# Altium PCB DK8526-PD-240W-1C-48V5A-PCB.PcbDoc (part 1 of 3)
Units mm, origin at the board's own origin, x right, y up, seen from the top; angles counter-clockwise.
Board outline 89.28 x 73.8 mm, 4 copper layers (Top Layer, Layer 1, Layer 2, Bottom Layer), stack 0.603 mm thick; 182 components, 162 nets, 518 pads, 506 vias.
Unrouted connection lines stored in the file: 4.
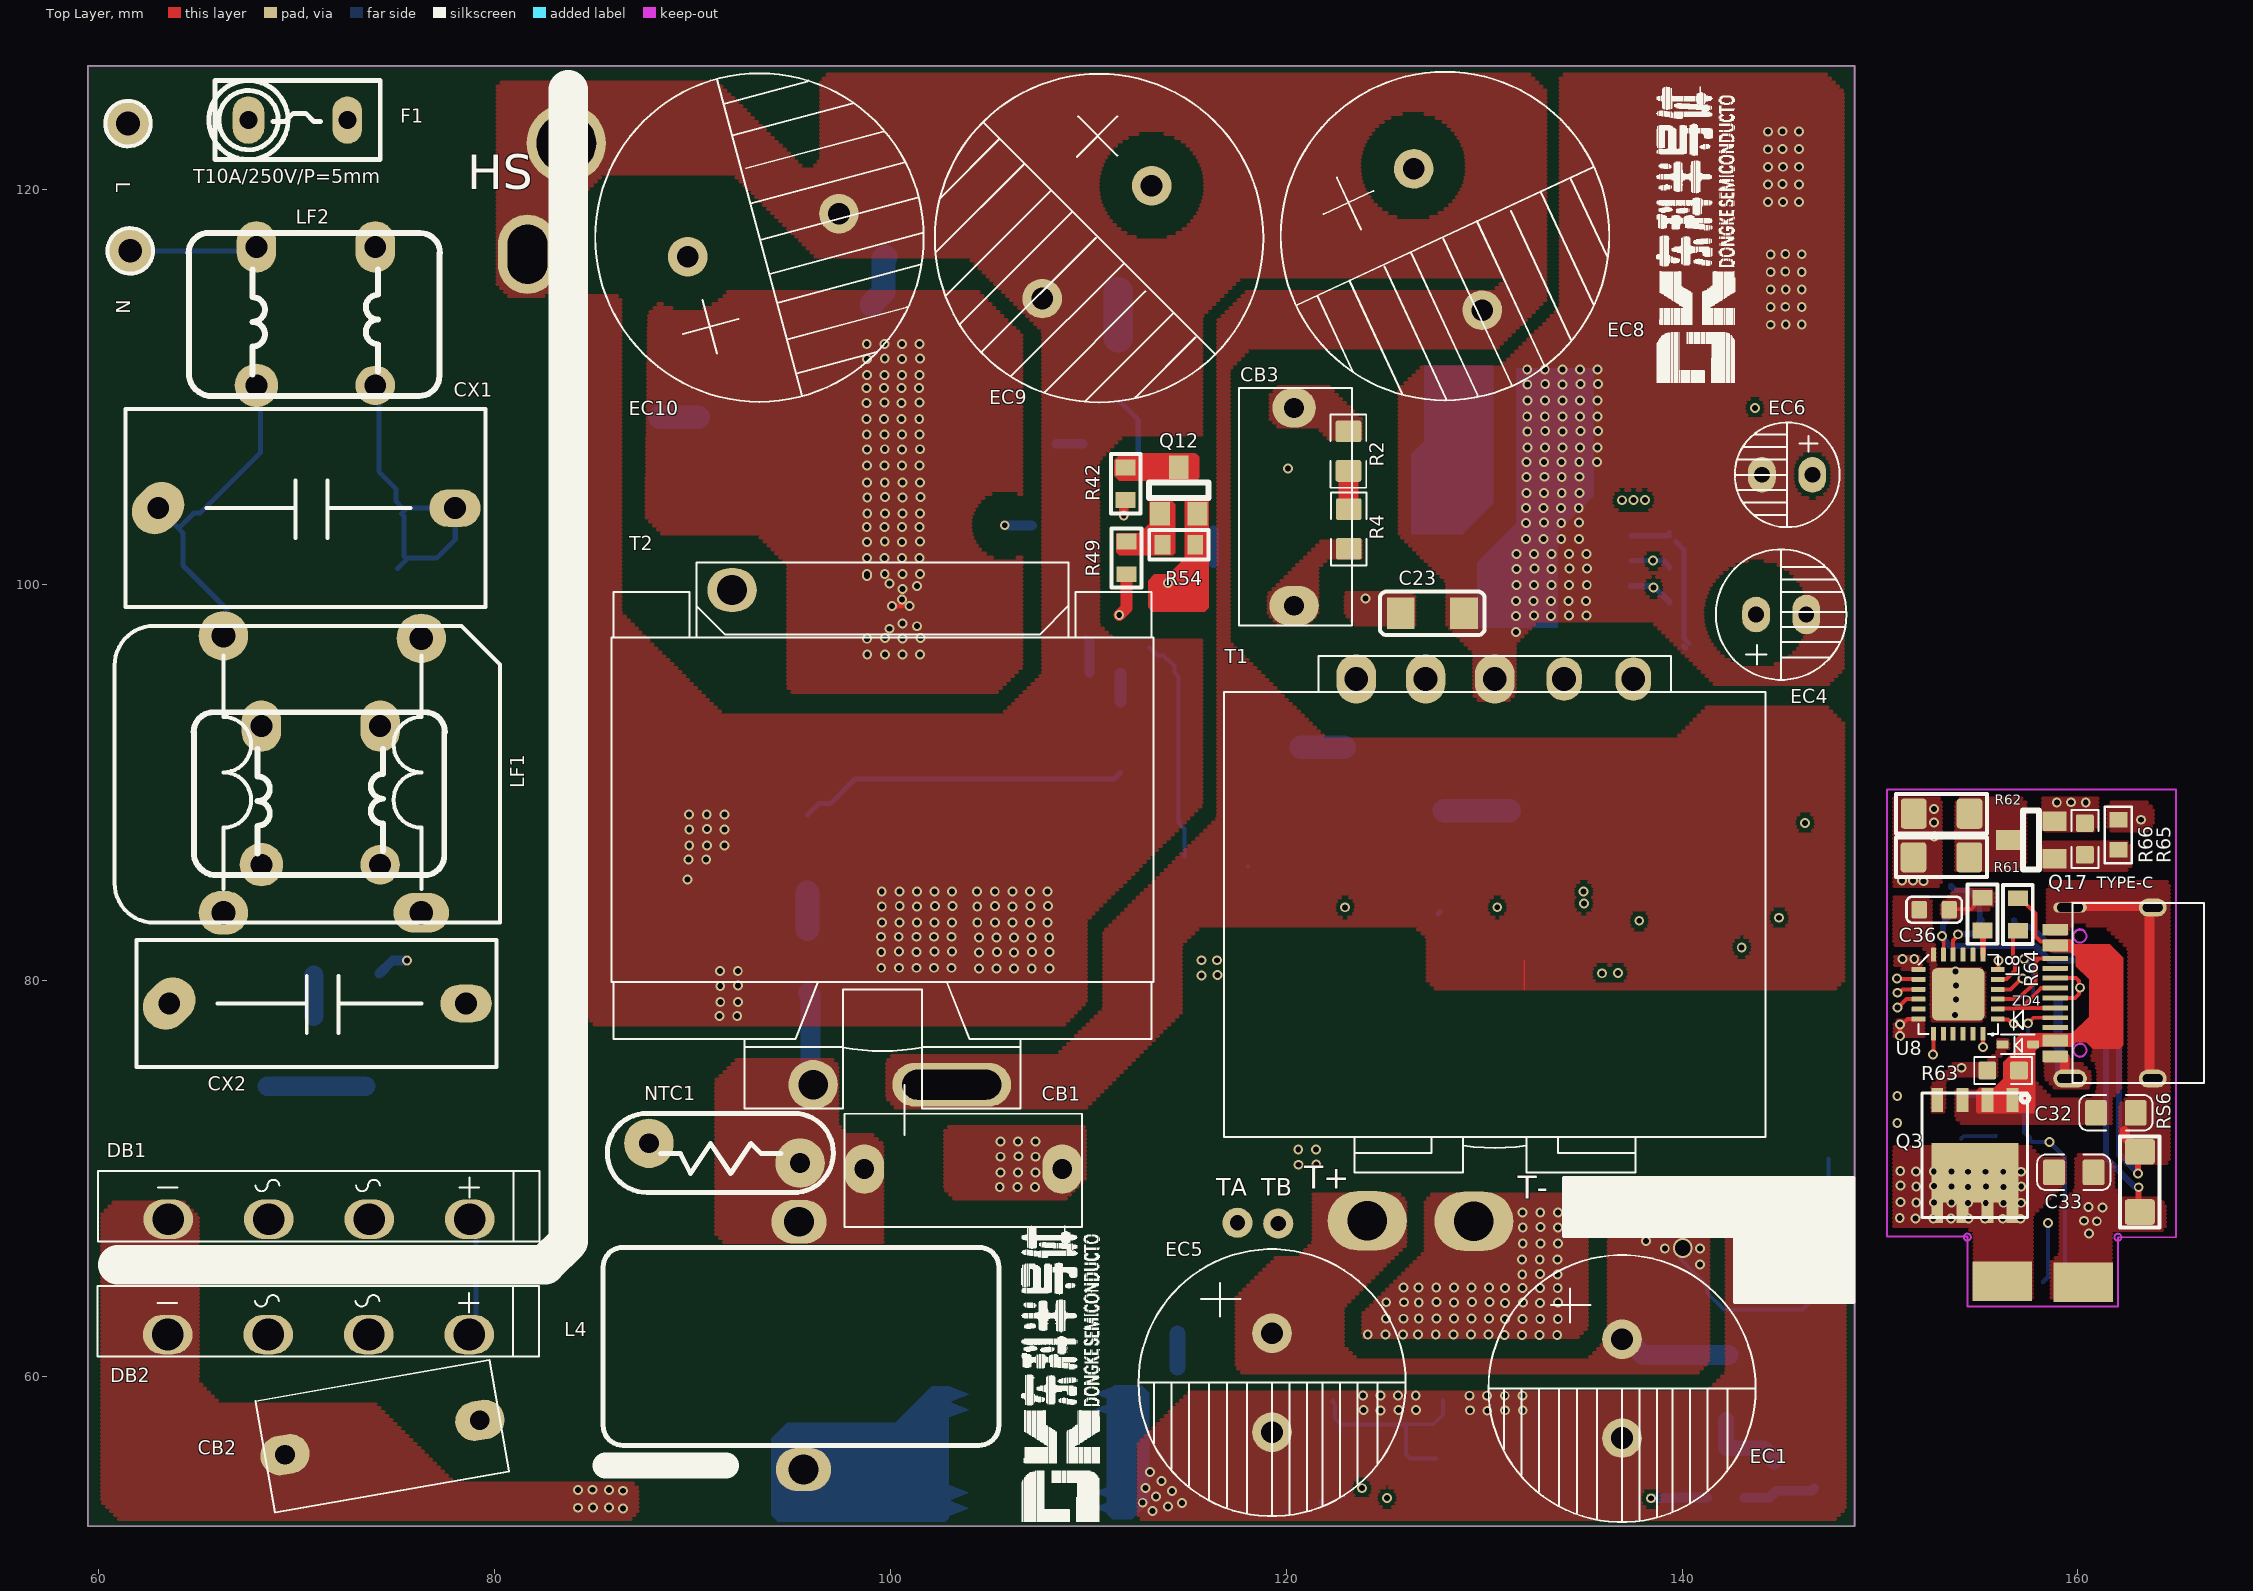
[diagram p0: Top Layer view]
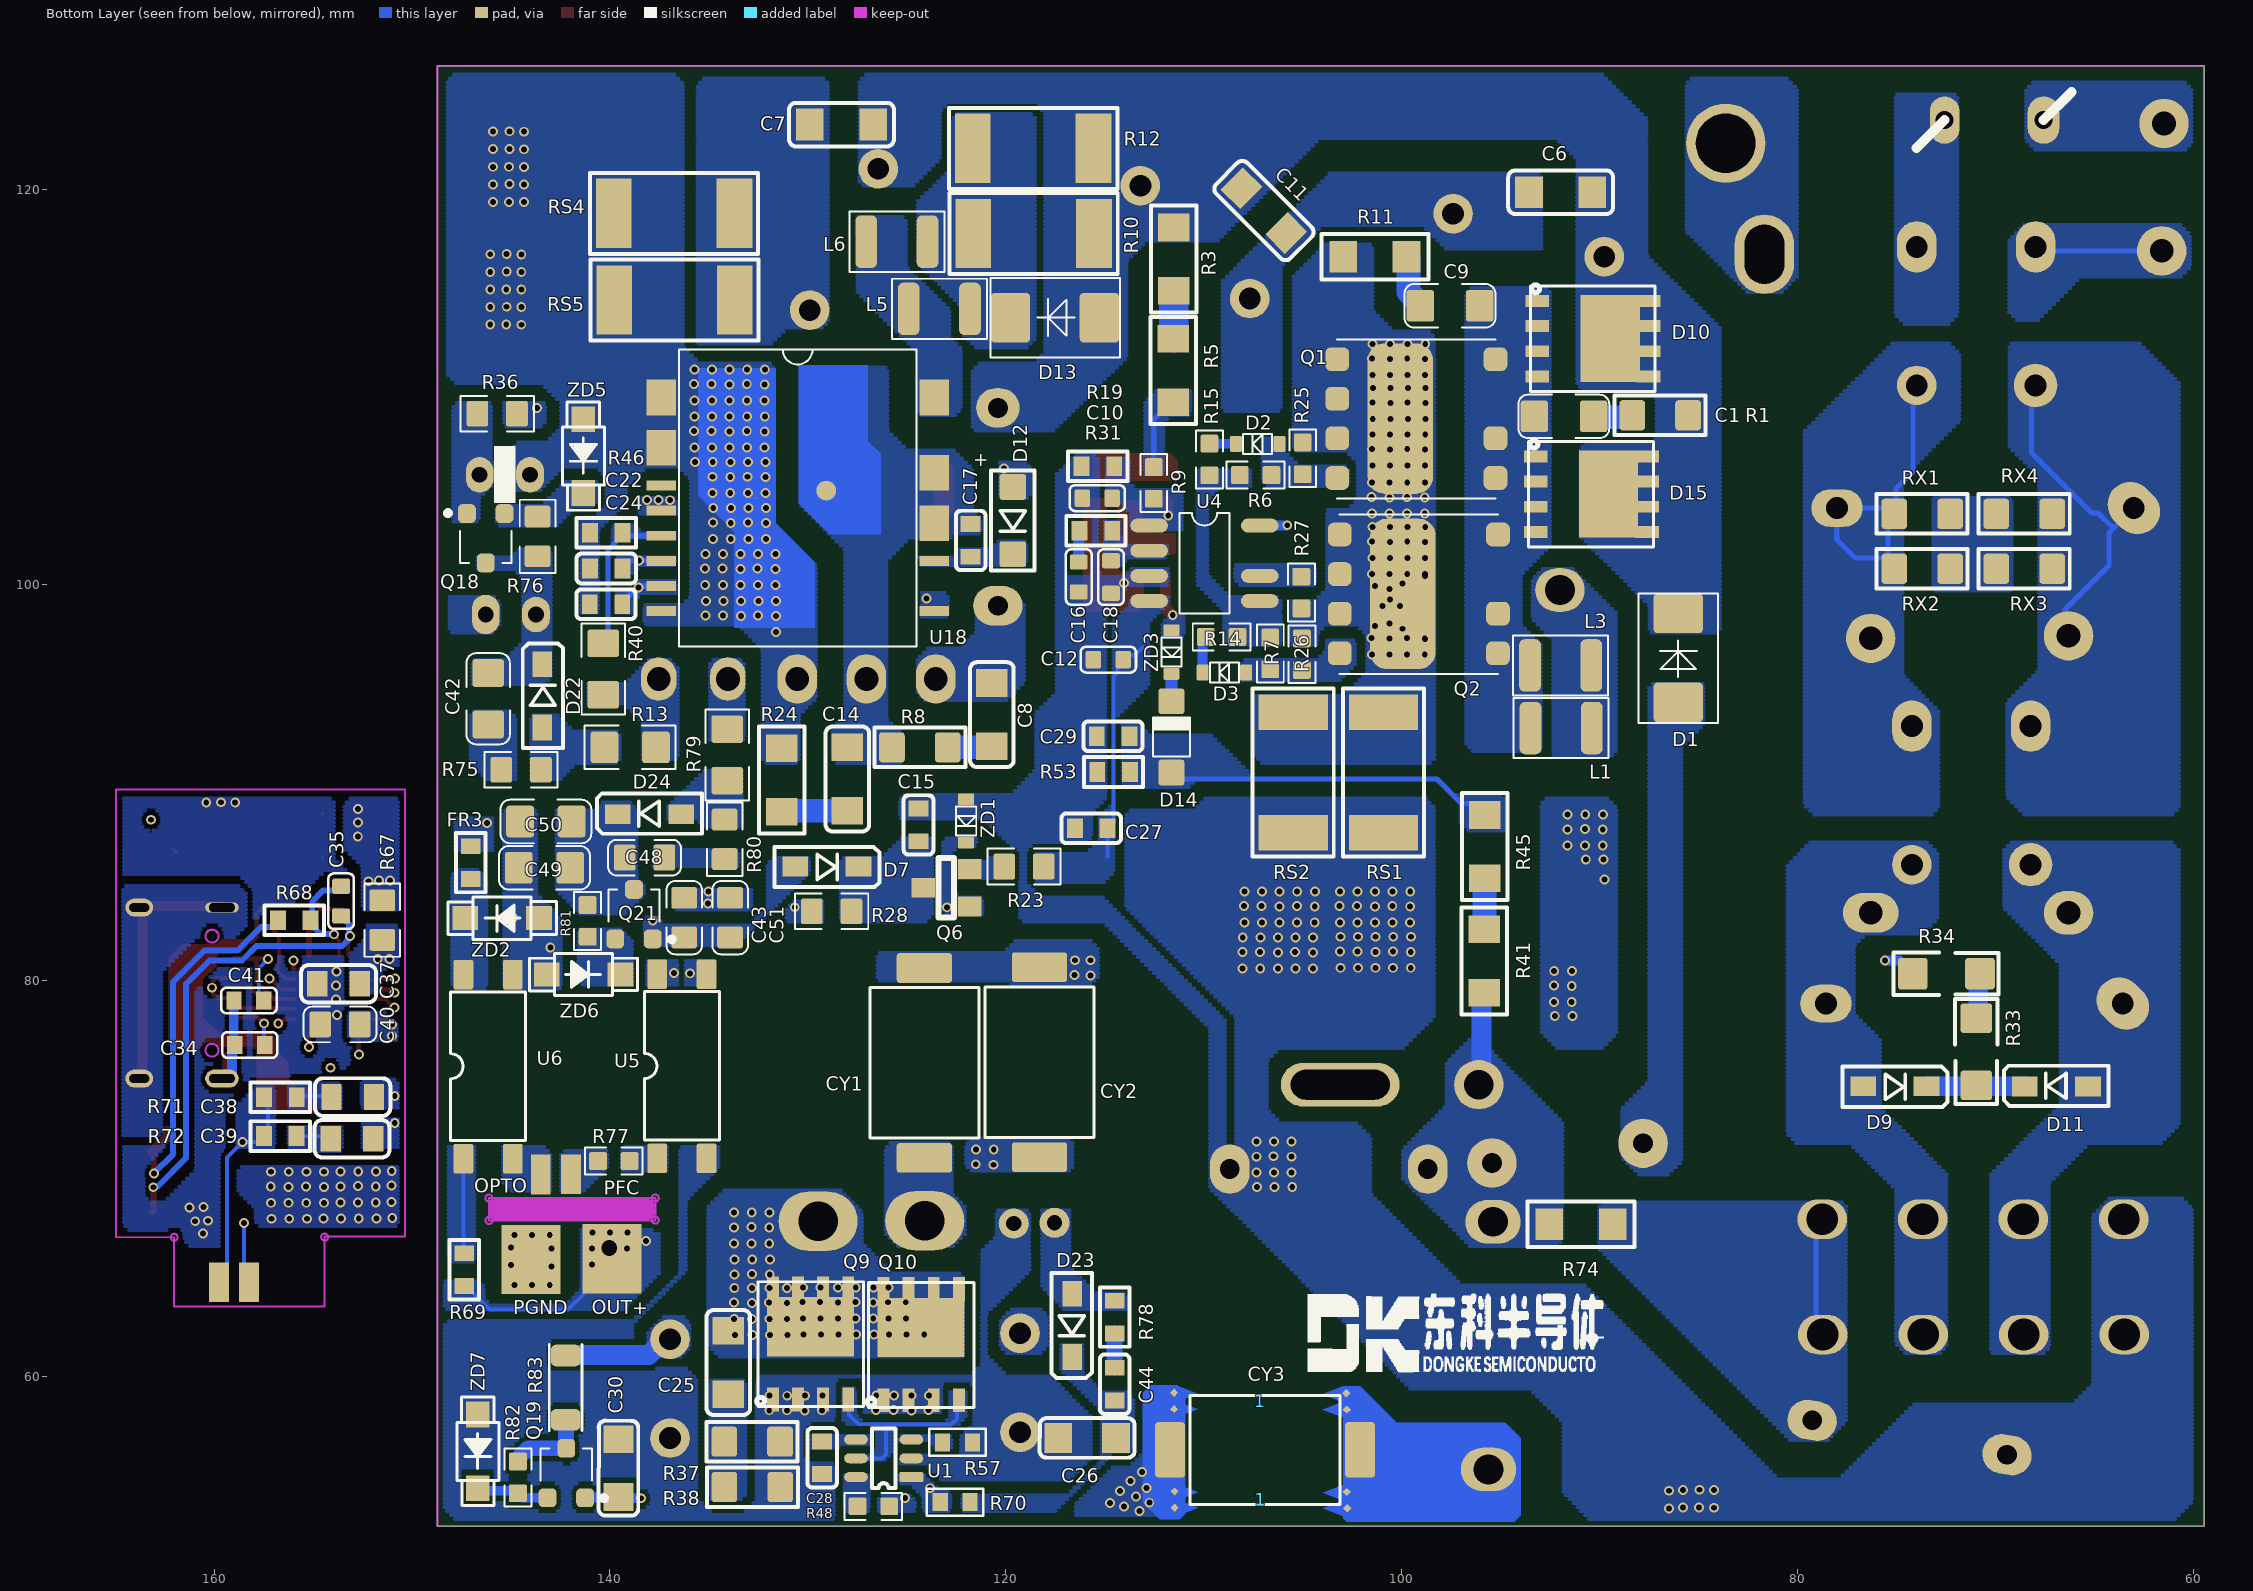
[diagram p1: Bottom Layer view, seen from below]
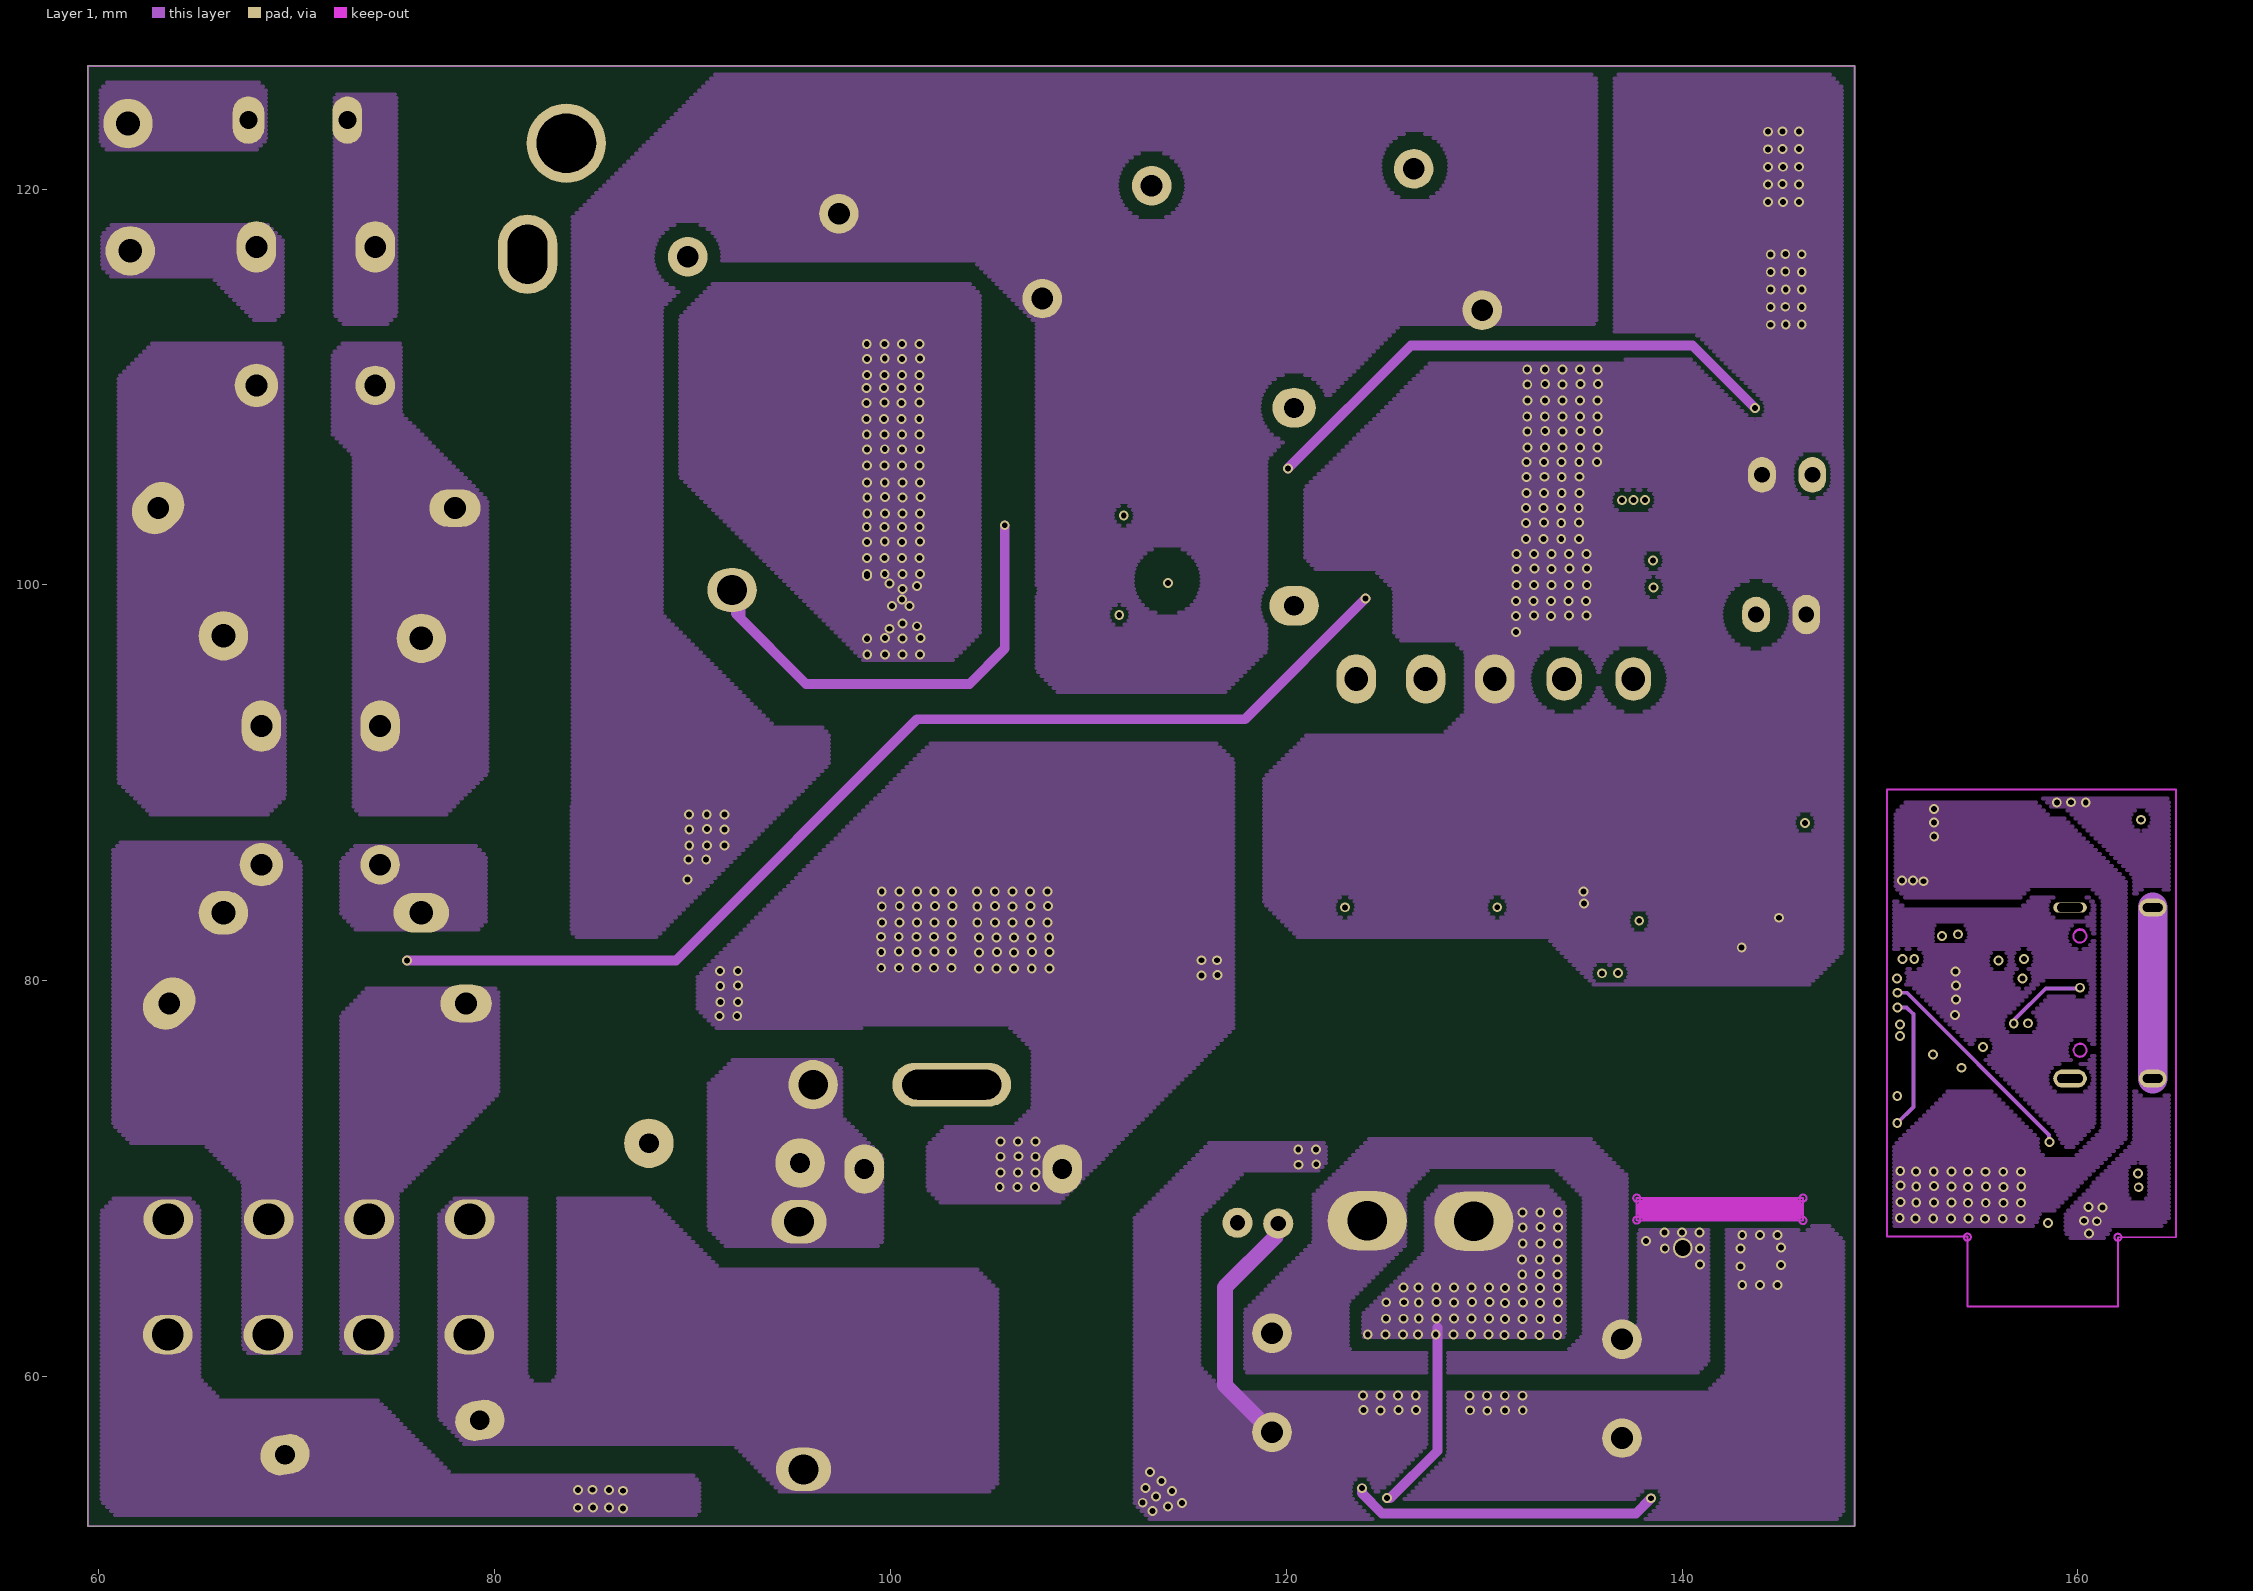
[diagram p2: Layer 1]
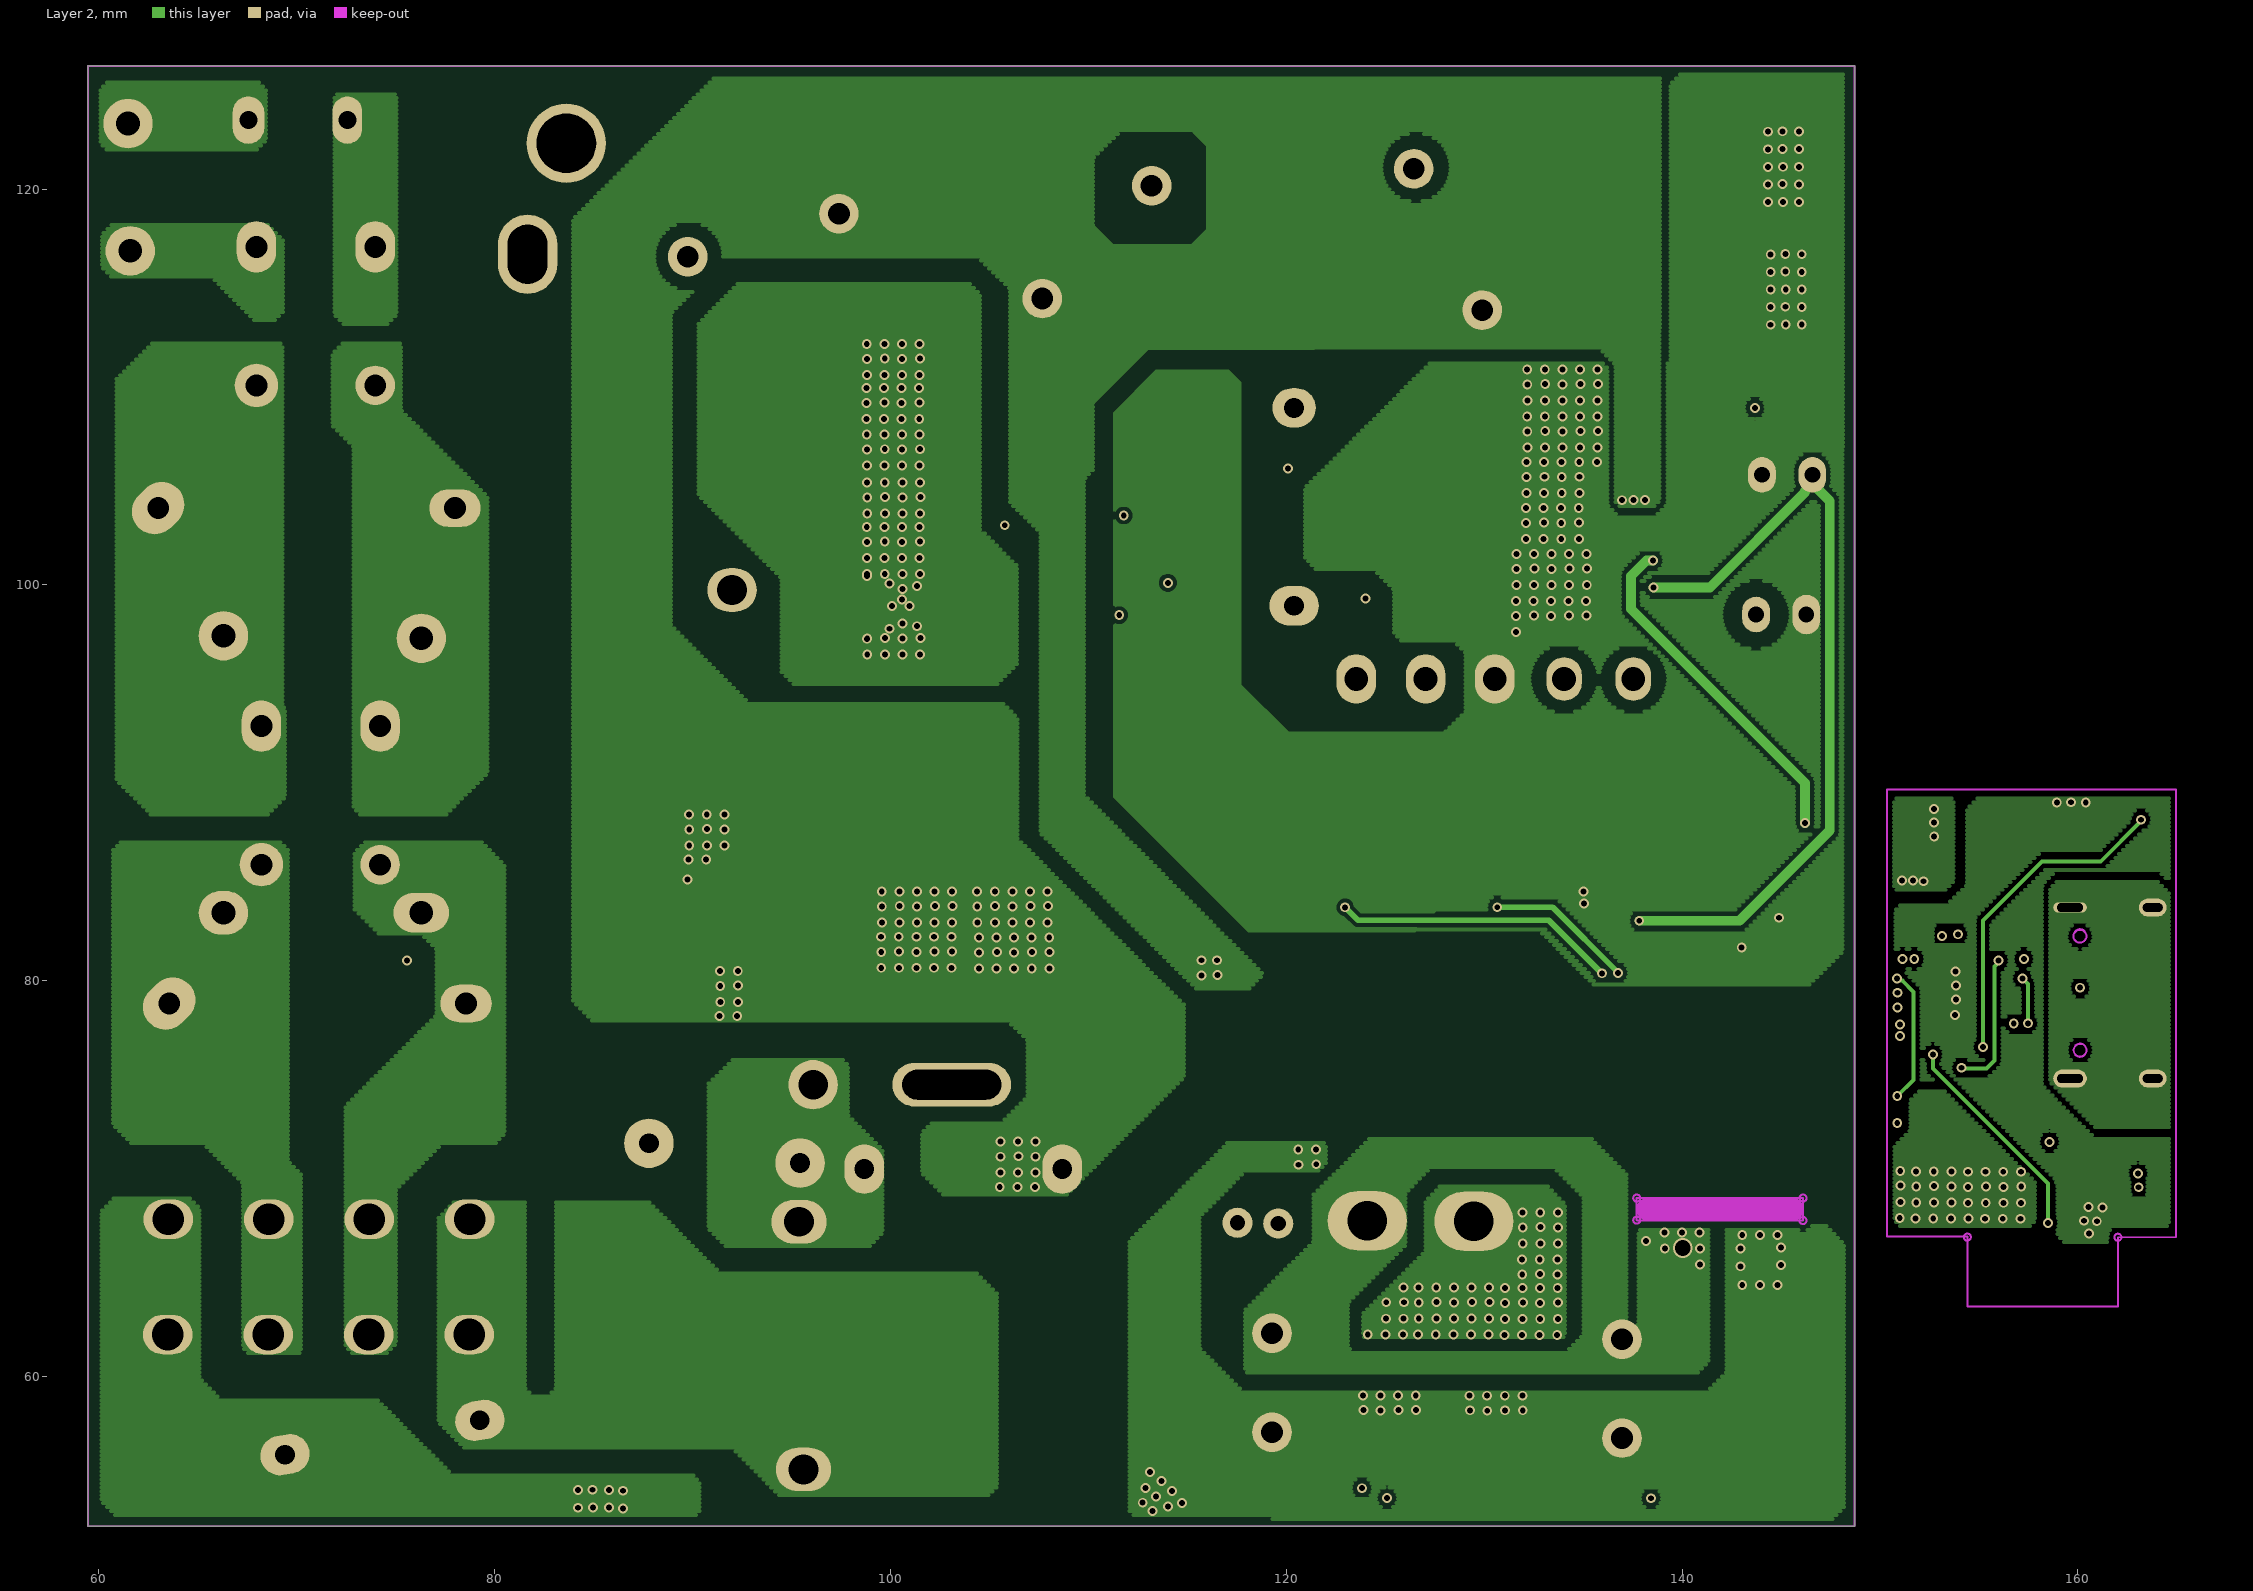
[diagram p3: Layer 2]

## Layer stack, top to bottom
Top Solder: solder mask 0.0102, Solder Resist, Dk 3.5
Top Layer: signal copper 0.0356
Dielectric 4: prepreg 0.0711, PP-006, Dk 4.1
Layer 1: signal copper 0.035
Dielectric 1: dielectric 0.32, FR-4, Dk 4.8
Layer 2: signal copper 0.035
Dielectric 5: prepreg 0.0711, PP-006, Dk 4.1
Bottom Layer: signal copper 0.0356
Bottom Solder: solder mask 0.0102, Solder Resist, Dk 3.5

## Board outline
59.436,52.434 148.717,52.434 148.717,126.229 148.717,126.238 59.436,126.238

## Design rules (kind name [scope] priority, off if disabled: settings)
Clearance [All] p1: gap=0.2 ignorepadtopadclearanceinfootprint=FALSE
PolygonConnect [All] p1: connectstyle=Direct reliefconductorwidth=0.254 reliefentries=4 polygonreliefangle="90 Angle" airgapwidth=0.254
RoutingVias [All] p1: holewidth=0.711 width=1.27 viastyle="Through Hole" minholewidth=0.711 minwidth=1.27 maxholewidth=0.711 maxwidth=1.27
SolderMaskExpansion [All] p1: expansion=0.102 istentingtop=FALSE
SupplyNets "Schematic Supply Nets_4" [InNet('HV')] p1: voltage=0.000
SupplyNets "Schematic Supply Nets_23" [InNet('SGND2')] p2: voltage=0.000
SupplyNets "Schematic Supply Nets_21" [InNet('SGND1')] p3: voltage=0.000
SupplyNets "Schematic Supply Nets_17" [InNet('48V')] p4: voltage=0.000
SupplyNets "Schematic Supply Nets_16" [InNet('Y3')] p5: voltage=0.000
SupplyNets "Schematic Supply Nets_15" [InNet('VS')] p6: voltage=0.000
SupplyNets "Schematic Supply Nets_14" [InNet('VOUT1')] p7: voltage=0.000
SupplyNets "Schematic Supply Nets_12" [InNet('VCC_EXT')] p8: voltage=0.000
SupplyNets "Schematic Supply Nets_11" [InNet('PGND')] p9: voltage=0.000
SupplyNets "Schematic Supply Nets_10" [InNet('VOUT')] p10: voltage=0.000
SupplyNets "Schematic Supply Nets_9" [InNet('SGND')] p11: voltage=0.000
SupplyNets "Schematic Supply Nets_8" [InNet('300V')] p12: voltage=0.000
SupplyNets "Schematic Supply Nets_7" [InNet('FB')] p13: voltage=0.000
SupplyNets "Schematic Supply Nets_2" [InNet('XCD')] p14: voltage=0.000
SupplyNets "Schematic Supply Nets_1" [InNet('GND')] p15: voltage=0.000
Width [All] p1: maxlimit=2 minlimit=0.2 preferedwidth=0.254
30 further rules are at their usual default settings.

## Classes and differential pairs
component class "协议部分原理图2026 01 21": C32 C34 C35 C36 C37 C38 C40 LED1 OP1 Q3 Q17 R61 R62 R63 R64 R65 R66 R67 R68 R69 R71 RT1 RV1 U5 U6 U8 ZD4
component class "Copy of DK8526-PD-240W-1C-48V5A-SCH": C6 C7 C8 C10 C12 C14 C15 C16 C17 C18 C22 C23 C24 C25 C28 C29 CB1 CB2 CX1 D1 D7 D9 D11 D12 D14 EC1 F1 FR3 L L3 L4 L5 L6 LF1 LF2 N NTC1 Q6 Q9 Q10 Q12 R1 R2 R3 R4 R5 R8 R9 R11 R19 R23 R24 R28 R31 R33 R34 R36 R37 R38 R40 R41 R42 R45 R46 R48 R49 R53 R54 R57 RS2 RS4 RS5 RS6 ZD1 ZD2 ZD3

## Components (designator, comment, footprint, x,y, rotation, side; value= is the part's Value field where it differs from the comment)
1 "" "SPARK GAP_6.3" 107.12,54.019 r180 bottom value=0307
1 "" "SPARK GAP_6.3" 107.146,59.008 r180 bottom value=0307
C1 "1206/47pF/1KV/±10%/X7R" C1206-H#1 93.099,108.52 r180 bottom (schematic designator C9)
C6 "1206/10nF/1KV/±10%/X7R" C1206-1_2 91.958,119.848 r270 bottom
C7 "NC" C1206-1_2 128.303,123.268 r270 bottom
C8 "NC" C1206-1_2 120.701,93.449 r0 bottom
C9 "1206/47pF/1KV/±10%/X7R" C1206-H#1 98.856,114.109 r180 bottom
C10 "0603/100pF/50V/±10%/X7R" C0603-T_3#1 115.377,104.388 r0 bottom
C11 "NC" C1206-1_2 106.952,118.922 r315 bottom (schematic designator C6)
C12 "0603/100nF/50V/±10%/X7R" C0603-T_3#1 114.818,96.226 r180 bottom
C14 "NC" C1206-1_2 128.003,90.195 r180 bottom
C15 "0603/1uF/50V/±10%/X7R" C0603-1 124.409,87.876 r0 bottom
C16 "0603/470nF/50V/±10%/X7R" C0603-T_3#1 116.311,100.407 r270 bottom
C17 "0603/470nF/50V/±10%/X7R" C0603-1 121.775,102.252 r180 bottom
C18 "0603/100nF/50V/±10%/X7R" C0603-T_3#2 114.683,100.399 r270 bottom
C22 "0603/1nF/50V/±10%/X7R" C0603-1 140.186,100.836 r270 bottom
C23 "1206/1nF/1KV/±10%/X7R" C1206-1_2 127.38,98.57 r90 top
C24 "0603/1uF/50V/±10%/X7R" C0603-1_2 140.202,99.024 r270 bottom
C25 "1206/470pF/250V/±10%/X7R" C1206-1_2 134.016,60.707 r0 bottom
C26 "NC" C1206-T 115.889,56.896 r0 bottom
C27 "NC" C0603-1 115.682,87.704 r90 bottom (schematic designator C15)
C28 "0603/1uF/50V/±10%/X7R" C0603-1 129.28,55.895 r0 bottom
C29 "0603/1uF/50V/±10%/X7R" C0603-1_2 114.579,92.359 r90 bottom
C30 "1206/4.7uF/50V/±10%/X7R" C1206-T 139.573,55.372 r90 bottom (schematic designator C26)
C32 "0805/1uF/63V/±10%/X7R" C0805-H 161.925,73.324 r180 top value=330pF
C33 "NC" C0805-H 159.797,70.318 r180 top value=330pF (schematic designator C32)
C34 "0603/330pF/50V/±10%/X7R" C0603-T 158.204,76.758 r180 bottom value=330pF
C35 "0603/1uF/50V/±10%/X7R" C0603-T_3#1 153.588,84.023 r90 bottom value=330pF
C36 "0603/1uF/50V/±10%/X7R" C0603-T_3#1 152.745,83.589 r0 top value=330pF
C37 "0805/100nF/100V/±10%/X7R" C0805-1_3 153.719,79.847 r0 bottom value=330pF
C38 "0805/100nF/100V/±10%/X7R" C0805-1_3 153.003,74.124 r180 bottom value=330pF
C39 "0805/3.3nF/100V/±10%/X7R" C0805-1_3 153.037,72.017 r180 bottom value=330pF
C40 "0805/100nF/100V/±10%/X7R" C0805-H 153.646,77.793 r0 bottom value=330pF
C41 "0603/330pF/50V/±10%/X7R" C0603-T 158.248,79.003 r180 bottom value=330pF (schematic designator C34)
C42 "NC" C1206-H#2 146.16,95.552 r270 bottom (schematic designator C22)
C43 "0805/10uF/50V/±10%/X7R" C0805-H 136.252,83.189 r90 bottom (schematic designator C24)
C44 "NC" C0603-1_2 114.496,59.614 r0 bottom (schematic designator C3)
C48 "NC" C0805-H 138.255,86.225 r180 bottom (schematic designator C22)
C49 "1206/4.7uF/50V/±10%/X7R" C1206-H#2 142.012,85.71 r0 bottom (schematic designator C22)
C50 "1206/4.7uF/50V/±10%/X7R" C1206-H#2 141.943,88.049 r0 bottom (schematic designator C22)
C51 "0805/10uF/50V/±10%/X7R" C0805-H 133.93,83.189 r90 bottom (schematic designator C24)
CB1 "155/450V/±5%/L7.5*11.5*12.5/P=10mm" CBB-MPB#1 103.679,70.485 r270 top
CB2 "155/450V/±5%/L7.5*11.5*12.5/P=10mm" CBB-MPB#2 74.324,56.917 r100 top
CB3 "684/450V/±5%/L7.5*11.5*12.5/P=10mm" CBB-MPB#3 120.396,103.951 r0 top (schematic designator CB2)
CX1 "105/310VAC/±20%/L18*10*12/P=15mm" CX15 78.342,103.886 r180 top
CX2 "224/310VAC/±20%/L18*6.5*12/P=15mm" CX15 78.901,78.849 r180 top (schematic designator CX1)
CY1 "471/400V/±10%/Y1/SMD" CY1-SMD 124.112,75.923 r270 bottom
CY2 "471/400V/±10%/Y1/SMD" CY1-SMD 118.296,75.962 r270 bottom
CY3 "221/400V/±10%/Y1/SMD" CY1-SMD 106.972,56.292 r180 bottom
D1 "ES5J/SMB" SMB 86.016,94.07 r0 bottom
D2 "1N4148/SOD-323" SOD-323 106.172,107.131 r0 bottom (schematic designator ZD3)
D3 "1N4148/SOD-323" SOD-323 107.85,95.579 r0 bottom (schematic designator ZD3)
D7 "1N4148/SOD-123" SOD-123-标 129.043,85.772 r180 bottom
D9 "F7/1A/1KV/SOD-123" SOD-123-标 75.072,74.669 r180 bottom
D10 "MSM06065G1/DFN5*6" "DFN5*6- mos" 87.514,114.351 r270 bottom (schematic designator Q9)
D11 "F7/1A/1KV/SOD-123" SOD-123-标 66.904,74.661 r0 bottom
D12 "ES1J/SOD-123" LL-34 119.642,103.257 r270 bottom
D13 "SS54/SMB" SMB 115.266,113.506 r270 bottom (schematic designator D1)
D14 "1N4148/SOD-123" SOD-123-H 111.628,90.521 r90 bottom
D15 "MSM06065G1/DFN5*6" "DFN5*6- mos" 87.598,106.496 r270 bottom (schematic designator Q9)
D22 "F7/1A/1KV/SOD-123" SOD-123-标 143.421,94.397 r90 bottom (schematic designator D7)
D23 "NC" SOD-123-标 116.636,62.581 r270 bottom (schematic designator D5)
D24 "F7/1A/1KV/SOD-123" SOD-123-标 138.004,88.418 r0 bottom (schematic designator D7)
DB1 "GBU1510/15A/1KV" "GBU 810" 71.078,69.079 r180 top
DB2 "GBU1510/15A/1KV" "GBU 810" 71.052,63.255 r180 top
EC1 "470uF/63V/L13*20/±20%/P=5mm/2000H" CE13X20L 136.969,59.412 r90 top locked
EC4 "10uF/200V/L6.3*12/±20%/P=2.5mm/2000H" CE6X12L 144.962,98.559 r180 top
EC5 "470uF/63V/L13*20/±20%/P=5mm/2000H" CE13X20L 119.282,59.712 r90 top
EC6 "10uF/100V/L5*11/±20%/P=2.5mm/2000H" CE5x11L 145.312,105.569 r0 top
EC8 "47uF/450V/L16*23/±20%/P=8mm/2000H" CE16x26L 128.023,117.632 r115 top
EC9 "47uF/450V/L16*23/±20%/P=8mm/2000H" CE16x26L 110.546,117.528 r45 top
EC10 "47uF/450V/L16*23/±20%/P=8mm/2000H" CE16x26L 93.38,117.56 r195 top
F1 "T10A/250V/P=5mm" FUSE8.5*4 70.055,123.493 r0 top
FR3 "0603/10Ω/±5%" R0603-T 147.034,85.973 r180 bottom
L "*" LN 61.468,123.317 r270 top (schematic designator L7)
L1 "1210/6A/0.05R@100MHz" 1210 91.933,92.771 r0 bottom
L3 "1210/6A/0.05R@100MHz" 1210 91.958,95.935 r0 bottom
L4 "100uH/L22mm*14mm*23mm/线径1mm/立式 锰锌" L8026 95.504,66.167 r180 top
L5 "1210/6A/0.05R@100MHz" 1210 123.356,113.952 r180 bottom
L6 "1210/6A/0.05R@100MHz" 1210 125.502,117.348 r180 bottom
L8 "0603/0Ω/±5%" R0603-T 155.186,83.371 r180 top
LF1 "10mH/L18*10*7/漆包线分绕/线径0.7mm/立式 锰锌" LF2 76.289,97.434 r180 top
LF2 "" CHOKE-10MMA 66.309,86.868 r90 top
LF2 "70uH/L10*6*4/漆包线与绝缘线并绕/线径0.8mm/立式 锰锌" CHOKE-10MMA 66.059,111.087 r90 top
N "*" LN 61.582,116.885 r270 top (schematic designator N1)
NTC1 "1D-11/P=7.5mm" THRP7.5 91.612,71.286 r0 top
Q1 "DK130G70/DFN8*8" "DK DFN8*8" 99.469,108.525 r180 bottom
Q2 "DK130G70/DFN8*8" "DK DFN8*8" 99.342,99.667 r180 bottom
Q3 "SLM150N06G/60V/2.2mΩ/PDFN5*6" "DFN5*6- mos" 156.709,68.351 r180 top (schematic designator Q16)
Q6 "MMBT5551/SOT-23" SOT-23-T 122.991,84.697 r90 bottom
Q9 "MIR15N7P4S1GC/150V/6.2mR/DFN5*6" "DFN5*6- mos" 131.77,64.464 r180 bottom
Q10 "MIR15N7P4S1GC/150V/6.2mR/DFN5*6" "DFN5*6- mos" 126.182,64.417 r180 bottom
Q12 "2N7002/SOT-23" SOT-23-T_2 114.565,104.771 r0 top
Q17 "2N7002/SOT-23" SOT-23-T_2 157.645,87.113 r90 top
Q18 "MMBT5551/SOT-23" SOT-23 146.281,102.363 r0 bottom
Q19 "MMBT5551/SOT-23" SOT-23 142.206,55.122 r180 bottom
Q21 "MMBT5551/SOT-23" SOT-23 138.787,83.363 r180 bottom
R1 "1206/22Ω/±5%" R1206-T_3#1 86.93,108.576 r0 bottom
R2 "0805/1MΩ/±5%" R0805-H 123.143,107.764 r270 top
R3 "1206/5.1MΩ/±5%" R1206-1 111.512,116.467 r0 bottom
R4 "0805/1MΩ/±5%" R0805-H 123.16,103.831 r270 top
R5 "1206/5.1MΩ/±5%" R1206-1 111.533,110.837 r0 bottom
R6 "0603/200Ω/±5%" R0603-H 108.173,105.557 r180 bottom (schematic designator R3)
R7 "0603/200Ω/±5%" R0603-H 106.631,97.342 r270 bottom (schematic designator R3)
R8 "NC" R1206-T_3#1 124.342,91.794 r0 bottom
R9 "0603/300KΩ/±5%" R0603-H 112.521,105.956 r270 bottom
R10 "2512/0.15Ω/±1%" R2512 118.59,117.762 r90 bottom (schematic designator RS5)
R11 "1206/22Ω/±5%" R1206-1 101.344,116.594 r270 bottom (schematic designator RS3)
R12 "2512/0.15Ω/±1%" R2512 118.613,122.066 r90 bottom (schematic designator RS5)
R13 "1206/1.2Ω/±5%" R1206-H 138.955,91.771 r180 bottom (schematic designator R4)
R14 "0603/10Ω/±5%" R0603-H 108.29,97.375 r0 bottom (schematic designator R3)
R15 "0603/10Ω/±5%" R0603-H 109.711,105.546 r90 bottom (schematic designator R3)
R19 "0603/82KΩ/±5%" R0603-T 115.344,105.996 r90 bottom
R23 "0805/4.7Ω/±5%" R0805-H 118.08,85.772 r0 bottom
R24 "NC" R1206-1_2 131.319,90.145 r180 bottom
R25 "0603/10KΩ/±5%" R0603-H 104.991,107.2 r270 bottom (schematic designator R3)
R26 "0603/10KΩ/±5%" R0603-H 105.037,97.302 r270 bottom (schematic designator R3)
R27 "0603/4.7KΩ/±5%" R0603-H 105.061,98.817 r90 bottom (schematic designator R3)
R28 "0805/10KΩ/±5%" R0805-H 129.799,83.51 r180 bottom
R31 "0603/100KΩ/±5%" R0603-T 115.443,102.743 r90 bottom
R33 "1206/10KΩ/±5%" R1206-锡膏 70.953,76.412 r90 bottom
R34 "1206/10KΩ/±5%" R1206-锡膏 72.466,80.357 r0 bottom
R36 "0805/2.2Ω/±5%" R0805-H 146.702,108.66 r180 bottom
R37 "1206/33Ω/±5%" R1206-T_2 132.817,56.71 r0 bottom
R38 "1206/33Ω/±5%" R1206-T_2 132.809,54.412 r0 bottom
R40 "1206/180KΩ/±1%" R1206-H 140.319,95.779 r90 bottom
R41 "1206/4.7MΩ/±5%" R1206-1_2 95.811,81 r0 bottom
R42 "0603/390KΩ/±5%" R0603-T 111.884,105.115 r0 top
R45 "1206/4.7MΩ/±5%" R1206-1_2 95.798,86.777 r0 bottom
R46 "0603/7.5KΩ/±1%" R0603-T 140.186,102.645 r270 bottom
R48 "0603/100Ω/±5%" R0603-H 127.492,53.441 r180 bottom
R49 "0603/10Ω/±5%" R0603-T 111.929,101.365 r0 top
R53 "0603/360KΩ/±5%" R0603-T 114.554,90.551 r90 bottom
R54 "0603/510KΩ/±5%" R0603-T 114.576,102.034 r90 top
R57 "NC" R0603-T_2 122.437,56.669 r0 bottom
R61 "1206/1KΩ/±5%" "R1206-T_2 - duplicate" 153.109,86.236 r180 top value=10K
R62 "1206/1KΩ/±5%" R1206-T_3#1 153.119,88.444 r180 top value=200R/0805
R63 "0603/1MΩ/±5%" R0603-H 155.429,75.463 r0 top value=200R/0805
R64 "0603/1KΩ/±5%" R0603-T 156.976,83.348 r180 top value=200R/0805
R65 "0603/510Ω/±5%" R0603-T_2 162.052,87.376 r90 top value=100K
R66 "0603/10KΩ/±5%" R0603-H 160.36,87.964 r270 top value=100K
R67 "0805/0Ω/±5%" R0805-H 151.508,82.063 r90 bottom value=100K
R68 "0603/330Ω/±1%" R0603-T 155.956,83.058 r90 bottom value=100K
R69 "0603/4.7KΩ/±5%" R0603-T 147.361,65.401 r0 bottom value=100K
R70 "NC" R0603-T_2 122.561,53.652 r180 bottom (schematic designator R60)
R71 "0603/1KΩ/±5%" R0603-T 156.658,74.118 r270 bottom value=10K
R72 "0603/1KΩ/±5%" R0603-T 156.663,72.15 r270 bottom value=10K
R74 "NC" R1206-1_2 90.932,67.691 r90 bottom (schematic designator R41)
R75 "NC" R0805-H 143.493,90.667 r0 bottom (schematic designator R40)
R76 "0805/120KΩ/±5%" R0805-H 143.661,103.458 r270 bottom (schematic designator R4)
R77 "0603/4.7KΩ/±5%" R0603-H 140.609,70.885 r180 bottom value=10K (schematic designator R73)
R78 "NC" R0603-T 114.497,63.004 r180 bottom (schematic designator R6)
R79 "1206/10Ω/±5%" R1206-H 134.104,91.388 r270 bottom (schematic designator R40)
R80 "NC" R0805-H 134.208,88.147 r270 bottom (schematic designator R40)
R81 "0603/51KΩ/±5%" R0603-H 141.131,83.825 r270 bottom (schematic designator R4)
R82 "0603/47KΩ/±5%" "R 0603 锡膏" 144.653,55.702 r270 bottom (schematic designator R4)
R83 "1206/10Ω/±5%" "R 1206 锡膏" 142.24,59.436 r270 bottom (schematic designator R4)
RS1 "2512/0.1Ω/±1%" R2512 100.915,90.523 r180 bottom
RS2 "2512/0.1Ω/±1%" R2512 105.474,90.523 r180 bottom
RS4 "2512/0.18Ω/±1%" R2512 136.759,118.78 r270 bottom
RS5 "2512/0.22Ω/±1%" R2512 136.74,114.404 r90 bottom
RS6 "1206/5mΩ/±1%" R1206-T_3#2 163.139,69.837 r90 top value=200R/0805 (schematic designator R62)
RX1 "1206/10MΩ/±5%" R1206-T_3#1 73.688,103.597 r0 bottom value=200R/0805 (schematic designator R62)
RX2 "1206/10MΩ/±5%" R1206-T_3#1 73.688,100.822 r0 bottom value=200R/0805 (schematic designator R62)
RX3 "1206/10MΩ/±5%" R1206-T_3#1 68.531,100.822 r0 bottom value=200R/0805 (schematic designator R62)
RX4 "1206/10MΩ/±5%" R1206-T_3#1 68.531,103.597 r0 bottom value=200R/0805 (schematic designator R62)
T1 "ATQ2718立式（5+0）" ATQ2718 130.541,83.35 r90 top
T2 "ATQ2714立式（5+2）" ATQ2714 99.594,88.347 r90 top
TYPE-C "TYPEC卧式贴片 16pin 长度7.4mm" TYPEC-全贴片式-ANKER 161.414,79.38 r90 top
U1 "DK3708A/SOT23-6" SOT23-6 124.769,54.916 r0 bottom
U4 "DK3603AG/SOP-7" SO-8 112.755,103.004 r180 bottom
U5 "EL1018/SOP-4" 贴片光耦 136.367,75.676 r270 bottom
U6 "EL1018/SOP-4" 贴片光耦 146.16,75.659 r270 bottom
U8 "HUSB368/QFN-24-4X4-0.5MM" QFN-24-4X4-0.5MM 151.955,80.568 r0 top
U18 "DK8526/ESOP-20" DK8730 131.263,103.859 r270 bottom
ZD1 "15V/SOD-323" SOD-323 122.006,89.176 r270 bottom (schematic designator D10)
ZD2 "6.8V/SOD-123" SOD-123 145.412,83.17 r0 bottom
ZD3 "6.2V/SOD-323" SOD-323 111.628,97.712 r270 bottom
ZD4 "15V/SOD-523" SOD523 156.971,76.788 r0 top (schematic designator D16)
ZD5 "15V/SOD-123" SOD-123 141.351,106.553 r270 bottom (schematic designator ZD2)
ZD6 "18V/SOD-123" SOD-123 141.374,80.312 r180 bottom (schematic designator ZD2)
ZD7 "15V/SOD-123" SOD-123 146.685,56.256 r270 bottom (schematic designator ZD2)

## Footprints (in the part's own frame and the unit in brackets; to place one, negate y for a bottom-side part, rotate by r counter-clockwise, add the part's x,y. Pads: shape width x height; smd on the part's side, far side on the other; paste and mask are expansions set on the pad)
1210 [mm] "SMD"
  rrect50% 1.1x2.65 smd mask+0.03: 1(-1.55,0) 2(1.55,0)
  silkscreen extent -2.4,-1.52 2.4,1.52, body extent -2.01,-1.02 1.92,1.02, height 0.25
ATQ2714 [mm]
  round 0 all layers, no hole: 1(11.4,-7.6) 1(11.4,-3.8) 1(11.4,0) 1(11.4,3.8)
  oval 2.2x2.5 hole 1.5: 5(11.4,7.6)
  round 2.5 hole 1.5: 6(-13.6,3.5)
  oval 2.2x6 hole 1.5 slot 5 at 90 deg unplated: 7(-13.6,-3.5)
  silkscreen extent -14.8,-13.7 12.8,13.7, body extent -14.77,-13.72 12.83,13.68, height 16.5
ATQ2718 [mm]
  oval 2.2x1.8 hole 1.2: 1(11.9,-7) 2(11.9,-3.5)
  round 0 all layers, no hole: 1(11.9,3.5)
  oval 2.5x2 hole 1.2: 3(11.9,0) 5(11.9,7)
  silkscreen extent -13.05,-13.68 13.05,13.67, body extent -5.21,-17.29 20.89,10.06, height 18.6
C0603-1 [mm]
  rect 1x0.8 smd: 1(0,-0.825) 2(0,0.825)
  silkscreen extent -0.75,-1.5 0.75,1.5, body extent -0.4,-0.8 0.4,0.8, height 0.8
C0603-1_2 [mm]
  rect 1x0.8 smd: 1(0,-0.825) 2(0,0.825)
  silkscreen extent -0.75,-1.5 0.75,1.5, body extent -0.4,-0.8 0.4,0.8, height 0.8
C0603-T [mm]
  rect 0.77x0.9 smd: 1(-0.755,0) 2(0.755,0)
  silkscreen extent -1.4,-0.65 1.4,0.65, body extent -0.8,-0.4 0.8,0.4, height 0.8
C0603-T_3#1 [mm]
  rrect25% 0.77x0.9 smd: 1(-0.755,0) 2(0.755,0)
  silkscreen extent -1.4,-0.65 1.4,0.65, body extent -0.8,-0.4 0.8,0.4, height 0.8
C0603-T_3#2 [mm]
  rrect25% 0.77x0.9 smd: 1(-0.828,0.003) 2(0.815,-0.001)
  silkscreen extent -1.4,-0.65 1.4,0.65, body extent -0.8,-0.4 0.8,0.4, height 0.8
C0805-1_3 [mm]
  rect 1.025x1.3 smd: 1(-1.075,0) 2(1.075,0)
  silkscreen extent -1.9,-0.95 1.9,0.95, body extent -1,-0.62 1,0.63, height 0.85
C0805-H [mm]
  rrect20% 1.1x1.3 smd: 1(-1,0) 2(1,0)
  silkscreen extent -1.85,-0.9 1.85,0.9, body extent -1.12,-0.72 1.08,0.73, height 1
C1206-1_2 [mm]
  rect 1.6x1.4 smd: 1(0,-1.6) 2(0,1.6)
  silkscreen extent -1.1,-2.65 1.1,2.65, body extent -0.8,-1.6 0.8,1.6, height 0.85
C1206-H#1 [mm]
  rrect20% 1.4x1.6 smd: 1(-0.194,0) 2(2.813,0.004)
  silkscreen extent -1,-1.1 3.6,1.1, body extent -0.59,-0.79 2.61,0.81, height 1
C1206-H#2 [mm]
  rrect20% 1.4x1.6 smd: 1(0,0) 2(2.6,0)
  silkscreen extent -1,-1.1 3.6,1.1, body extent -0.42,-0.95 3.08,0.95, height 1.25
C1206-T [mm]
  rect 1.4x1.524 smd: 1(-1.462,0)
  rect 1.4x1.5 smd: 2(1.462,0)
  silkscreen extent -2.4,-1 2.4,1, body extent -1.6,-0.8 1.6,0.8, height 1.8
CBB-MPB#1 [mm]
  oval 2.5x2 hole 1: 1(0,5) 2(0,-5)
  silkscreen extent -2.79,-6 2.92,6
CBB-MPB#2 [mm]
  oval 2x2.5 hole 1: 1(0,5) 2(0,-5)
  silkscreen extent -2.79,-6 2.92,6
CBB-MPB#3 [mm]
  oval 2.2x2 hole 1: 1(0,5)
  oval 2.5x2 hole 1: 2(0,-5)
  silkscreen extent -2.79,-6 2.92,6
CE5x11L [mm] "EC"
  oval 1.4x1.8 hole 0.8: 1(1.275,0) 2(-1.275,0)
  silkscreen extent -2.65,-2.65 2.65,2.65, body extent -2.7,-2.7 2.7,2.7, height 11.5
CE6X12L [mm] "EC"
  oval 1.4x1.8 hole 0.8: 1(1.22,0.052)
  oval 1.4x2 hole 0.8: 2(-1.32,0.052)
  silkscreen extent -3.35,-3.24 3.25,3.35, body extent -3.35,-3.25 3.25,3.35, height 12.5
CE13X20L [mm]
  round 2 hole 1.1: 1(2.475,0) 2(-2.525,0)
  silkscreen extent -6.77,-6.75 6.72,6.75, body extent -6.82,-6.77 6.67,6.72, height 20.5
CE16x26L [mm]
  round 2 hole 1.1: 0(-4.191,-0.127) 1(3.75,0)
  silkscreen extent -8.3,-8.3 8.3,8.3, body extent -8.3,-8.27 8.3,8.32, height 26.6
CHOKE-10MMA [mm]
  oval 2.6x2 hole 1.1: 1(6,-7.9) 4(6,-1.9)
  round 2 hole 1.1: 2(-1,-7.9)
  round 2.2 hole 1.1: 3(-1,-1.9)
  silkscreen extent -1.53,-11.17 6.7,1.52
CX15 [mm]
  oval 2.6x1.9 hole 1.1: 1(0.35,0)
  oval 2.8x2.3 hole 1.1 rot 45: 2(15.35,0)
  silkscreen extent -1.2,-5 17,5
CY1-SMD [mm]
  rrect20% 1.5x2.8 smd: 1(-4.725,0) 2(4.875,0)
  silkscreen extent -3.73,-2.75 3.87,2.75, body extent -4.8,-2.72 5,2.78, height 2.52
"DFN5*6- mos" [mm]
  rect 0.6x1.2 smd: 1(0,-5.621) 2(1.27,-5.621) 3(2.54,-5.621) 4(3.81,-5.621) 5(3.81,0) 6(2.54,0) 7(1.27,0) 8(0,0)
  rect 4.4x3 smd: 9(1.897,-1.943)
  silkscreen extent -0.82,-5.98 4.58,0.32
DK8730 [mm]
  rect 1.8x1.5 smd: 1GND(-5.615,-6.151) 2GND(-3.075,-6.151) 11HB(0.735,7.646) 12HB(-1.805,7.646) 13VIN(-5.615,7.646)
  rect 0.5x1.5 smd: 3NC(-1.17,-6.151) 4CS(0.1,-6.151) 5VS(1.37,-6.151) 6FB(2.64,-6.151) 7VCC(3.91,-6.151) 8GND(5.18,-6.151) 9XCD(5.18,7.646) 10VCCH(2.64,7.646)
  round 1 smd: 14HB(-0.909,2.195)
  round 0.025 smd: 15GND(-0.539,-1.332)
  Top Layer region: -7.253,4.298 -3.405,4.298 -2.762,4.941 1.297,4.941 1.297,2.353 1.281,2.353 -0.274,0.798 -7.253,0.798
  Top Layer region: -7.089,-0.367 -7.089,-4.267 -0.652,-4.267 1.168,-2.448 6.011,-2.448 6.011,1.602 2.701,1.602 0.732,-0.367
  silkscreen extent -8.03,-5.25 6.97,6.75
"DK DFN8*8" [mm]
  rrect50% 1.2x1.2 smd: 1(-3.781,2.885) 2(-3.781,0.885) 3(-3.781,-1.115) 4-G(-3.781,-3.115) 5(4.219,-3.115) 6(4.219,-1.115) 8(4.219,2.885)
  rrect50% 3.3x7.6 smd: 9(-0.591,-0.115)
  silkscreen extent -3.78,-4.17 4.22,3.88, body extent -3.77,-4.15 4.23,3.85, height 1.4
FUSE8.5*4 [mm]
  oval 1.6x2.4 hole 0.9: 1(-2.5,0)
  oval 1.5x2.4 hole 0.9: 2(2.5,0)
  silkscreen extent -4.5,-2 4.16,2
"GBU 810" [mm]
  oval 2.5x2 hole 1.6: 1(-7.662,1.134) 2(-2.582,1.134) 3(2.498,1.134) 4(7.578,1.134)
  silkscreen extent -11.18,-1.32 11.13,2.25, body extent -11.2,-1.33 11.1,2.23, height 21.4
L8026 [mm]
  oval 2.8x2.2 hole 1.5: 1(-0.099,10.861) 2(0.127,-1.651)
  silkscreen extent -9.97,-0.36 10.03,9.64
LF2 [mm]
  oval 2.5x2.2 hole 1.2: 1(10,14)
  round 2.5 hole 1.2: 2(10,0) 3(0,0.127)
  oval 2.8x2 hole 1.2: 4(0,14)
  silkscreen extent -3.98,-0.5 15.5,14.5
LL-34 [mm]
  rrect20% 1.3x1.35 smd mask+0.05: A(-1.7,0) K(1.7,0)
  silkscreen extent -2.52,-1.1 2.52,1.1, body extent -1.76,-0.75 1.74,0.75, height 1.49
LN [mm]
  round 2.5 hole 1.2 mask+0.03: 1(0,0)
  silkscreen extent -1.15,-1.15 1.15,1.15
QFN-24-4X4-0.5MM [mm]
  rrect20% 0.7x0.25 smd paste+0 mask+0.05: 1(0,0) 2(0,-0.5) 3(0,-1) 4(0,-1.5) 5(0,-2) 6(0,-2.5) 13(4,-2.5) 14(4,-2) 15(4,-1.5) 16(4,-1) 17(4,-0.5) 18(4,0)
  rrect20% 0.25x0.7 smd paste+0 mask+0.05: 7(0.75,-3.25) 8(1.25,-3.25) 9(1.75,-3.25) 10(2.25,-3.25) 11(2.75,-3.25) 12(3.25,-3.25) 19(3.25,0.75) 20(2.75,0.75) 21(2.25,0.75) 22(1.75,0.75) 23(1.25,0.75) 24(0.75,0.75)
  rrect20% 2.65x2.65 smd paste+0 mask+0.05: 25(2.002,-1.254)
  silkscreen extent 0,-3.25 4,0.75, body extent 0.01,-3.25 4.01,0.75, height 0.75
R0603-H [mm]
  rrect20% 0.9x0.9 smd: 1(0,0) 2(1.6,0)
  silkscreen extent -0.66,-0.68 2.26,0.68, body extent -0.05,-0.47 1.7,0.48, height 0.5
R0603-T [mm]
  rect 1x0.8 smd: 1(0,-0.825) 2(0,0.825)
  silkscreen extent -0.75,-1.5 0.75,1.5, body extent -0.4,-0.8 0.4,0.8, height 0.8
R0603-T_2 [mm]
  rect 0.77x0.9 smd: 1(-0.755,0) 2(0.755,0)
  silkscreen extent -1.43,-0.68 1.43,0.68, body extent -0.8,-0.4 0.8,0.4, height 0.45
R0805-H [mm]
  rrect20% 1.1x1.3 smd: 1(0,0) 2(2,0)
  silkscreen extent -0.85,-0.9 2.85,0.9, body extent -0.1,-0.7 2.1,0.7, height 0.6
R1206-1 [mm]
  rect 1.6x1.4 smd: 1(0,-1.6) 2(0,1.6)
  silkscreen extent -1.15,-2.7 1.15,2.7, body extent -0.8,-1.55 0.8,1.55, height 0.55
R1206-1_2 [mm]
  rect 1.6x1.4 smd: 1(0,-1.6) 2(0,1.6)
  silkscreen extent -1.15,-2.7 1.15,2.7, body extent -0.8,-1.55 0.8,1.55, height 0.55
R1206-H [mm]
  rrect20% 1.4x1.6 smd: 1(-1.325,0.025) 2(1.275,0.025)
  silkscreen extent -2.33,-1.07 2.28,1.13, body extent -1.72,-0.85 1.68,0.9, height 0.65
R1206-T_2 [mm]
  rrect25% 1.3x1.525 smd: 1(-1.412,0) 2(1.412,0)
  silkscreen extent -2.3,-1 2.3,1, body extent -1.55,-0.8 1.55,0.8, height 0.55
"R1206-T_2 - duplicate" [mm]
  rrect25% 1.3x1.525 smd: 1(-1.412,0) 2(1.412,0)
  silkscreen extent -2.3,-1 2.3,1, body extent -1.55,-0.8 1.55,0.8, height 0.55
R1206-T_3#1 [mm]
  rrect25% 1.3x1.525 smd: 1(-1.412,0) 2(1.412,0)
  silkscreen extent -2.3,-1 2.3,1, body extent -1.55,-0.8 1.55,0.8, height 0.55
R1206-T_3#2 [mm]
  rrect25% 1.3x1.525 smd: 1(-1.524,0) 2(1.524,0)
  silkscreen extent -2.3,-1 2.3,1, body extent -1.55,-0.8 1.55,0.8, height 0.55
R1206-锡膏 [mm]
  rrect20% 1.5x1.6 smd mask+0.05: 1(-1.7,0) 2(1.7,0)
  silkscreen extent -2.64,-1.07 2.67,1.07
R2512 [mm]
  rect 3.5x1.8 smd: 1(0,-3.05) 2(0,3.05)
  silkscreen extent -2.05,-4.25 2.05,4.25, body extent -1.6,-3.2 1.6,3.15, height 0.55
"R 0603 锡膏" [mm] "AI090;"
  rrect20% 0.9x0.9 smd: 1(0,0) 2(1.6,0)
  silkscreen extent -0.66,-0.68 2.26,0.68, body extent -0.07,-0.48 1.68,0.48, height 0.5
"R 1206 锡膏" [mm] "AI092;"
  rrect50% 1.1x1.5 smd: 1(-1.625,0) 2(1.625,0)
  silkscreen extent -2.18,-0.83 2.17,0.83, body extent -1.67,-0.87 1.73,0.87, height 0.65
SMB [mm]
  rrect20% 2.5x2 smd: 1(0,0) 2(0,-4.5)
  silkscreen extent -2.01,-5.5 2,1.05, body extent -1.8,-4.91 1.8,0.39, height 2.35
SO-8 [mm]
  oval 1.9x0.7 smd: 1FB(0,0) 2COMP(0,-1.27) 3GND(0,-2.54) 4VCC(0,-3.81) 5GATE(5.588,-3.81) 6CS(5.588,-2.54) 8HV(5.588,0)
  oval 1.9x0.7 on Bottom Overlay: 7NC(5.588,-1.27)
  silkscreen extent 1.52,-4.45 4.06,0.64, body extent -0.28,-4.41 5.97,0.65, height 1.76
SOD523 [mm] "TY041;"
  rrect20% 0.6x0.4 smd mask+0: 1(-0.775,0) 2(0.775,0)
  silkscreen extent -1.32,-0.5 0.85,0.55, body extent -0.8,-0.39 0.8,0.4, height 0.7
SOD-123 [mm]
  rect 1.3x1.2 smd: 1(-1.825,0) 2(1.9,0)
  silkscreen extent -2.7,-1.06 2.78,1.07
SOD-123-H [mm]
  rrect20% 1.3x1.3 smd: 1(0,0) 2(3.6,0)
  silkscreen extent 0.81,-0.95 2.79,0.94, body extent -0.05,-0.8 3.65,0.8, height 1.25
SOD-123-标 [mm]
  rect 1.3x1 smd mask+0.05: A(-1.6,0) K(1.6,0)
  silkscreen extent -2.64,-1.04 2.66,0.99, body extent -1.92,-0.87 1.93,0.83, height 1.42
SOD-323 [mm]
  rrect20% 0.6x0.8 smd mask+0: 1(0,0) 2(2.2,0)
  silkscreen extent 0.37,-0.5 1.84,0.51, body extent -0.15,-0.62 2.35,0.63, height 0.9
SOT23-6 [mm]
  rrect20% 1.2x0.5 smd mask+0: "1  HVCC"(0,0)
  oval 1.2x0.5 smd mask+0: 2GND(0,-0.95) "3 TW"(0,-1.9) 4VDD(2.8,-1.9) 5GT(2.8,-0.95) "6K SRD"(2.8,0)
  silkscreen extent 0.81,-2.45 1.99,0.55, body extent -0.06,-2.44 2.75,0.56, height 1.15
SOT-23 [mm]
  rrect50% 0.9x0.95 smd: 1E(0.95,-1.25) 2C(0,1.25) 3B(-0.95,-1.25)
  silkscreen extent -1.3,-1.39 2.03,1.25
SOT-23-T [mm]
  rect 1x1.2 smd: 1(-0.95,-1.175) 2(0.95,-1.175) 3(0,1.175)
  silkscreen extent -1.5,-0.39 1.5,0.42, body extent -1.45,-1.2 1.45,1.2, height 1
SOT-23-T_2 [mm]
  rect 1x1.2 smd: 1(-0.95,-1.175) 2(0.95,-1.175) 3(0,1.175)
  silkscreen extent -1.5,-0.39 1.5,0.42, body extent -1.45,-1.2 1.45,1.2, height 1
"SPARK GAP_6.3" [mm]
  rect 0.3x0.3 smd rot 135 mask+0: 1(4.35,0.15) 1(4.375,-0.675)
  rect 0.3x0.3 smd rot 45 mask+0: 2(-4.35,-0.65) 2(-4.35,0.175)
  Top Layer region: -3.15,-0.65 -4.184,-1.05 -4.184,-0.25
  Top Layer region: -4.184,0.525 -4.699,0.525 -4.699,-1.05 -4.184,-1.05 -4.075,-0.941 -4.075,0.416
  Top Layer region: -3.15,0.125 -4.184,0.525 -4.184,-0.275
  Top Layer region: 3.15,0.1 4.184,0.5 4.184,-0.3
  Top Layer region: 4.184,0.5 4.699,0.5 4.699,-1.075 4.184,-1.075 4.075,-0.966 4.075,0.391
  Top Layer region: 3.15,-0.675 4.184,-1.075 4.184,-0.275
THRP7.5 [mm]
  round 2.5 hole 1: 1(-3.82,0.5) 2(3.82,-0.5)
  oval 2.3x0.6 on Bottom Overlay rot 135: 2(-4.4,1.17) 3(4.34,-1.15)
  silkscreen extent -5.92,-1.99 5.5,2.01
TYPEC-全贴片式-ANKER [mm]
  rrect20% 0.6x1.3 smd mask+0: A1B12(-3.2,2.555) A4B9(-2.4,2.555) B1A12(3.2,2.555) B4A9(2.4,2.555)
  rrect20% 0.25x1.3 smd mask+0: A5CC1(-1.25,2.555) A6DP(-0.25,2.555) A7DM(0.25,2.555) A8(1.25,2.555) B5CC2(1.75,2.555) B6DP(0.75,2.555) B7DM(-0.75,2.555) B8(-1.75,2.555)
  oval 0.9x1.4 hole 0.45 slot 1 at 90 deg: H(-4.32,-2.375) H(4.32,-2.375)
  oval 0.9x1.7 hole 0.45 slot 1.3 at 90 deg: H(-4.32,1.805)
  oval 0.5x1.7 hole 0.45 slot 1.3 at 90 deg: H(4.32,1.805)
  Keep-Out Layer circle w0.05: c2.89,1.305 r0.35
  Keep-Out Layer circle w0.05: c-2.89,1.305 r0.35
  silkscreen extent -4.55,-4.98 4.55,1.68
贴片光耦 [mm]
  rrect20% 1.5x1 smd: 1(4.65,-1.25) 2(4.65,1.25) 3(-4.65,1.25) 4(-4.65,-1.25)
  silkscreen extent -3.77,-1.9 3.73,1.9

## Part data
1 1: library part PE-SCH
C1 C8 C9 C10 C12 C15 C16 C17 C18 C22 C24 C25 C27 C28 C42 C43 C44 C48 C49 C50 C51: library part CAPACITOR_0603, "贴片电容"
C6 C7 C11 C14 C23: library part CAPACITOR_1206, "贴片电容"
C26 C29 C30: library part CAP, "贴片电容"
C32 C33 C34 C35 C36 C37 C38 C39 C40 C41: library part Cap, "贴片电容"
CB1 CB2 CB3: library part CAPACITOR_0603, "CBB电容"
CX1 CX2: library part "CAPACITOR_ XCAP", "插件X电容"
CY1 CY2 CY3: "贴片Y电容"
D1 D7 D9 D11 D12 D22 D23 D24: library part D0, "贴片二极管"
D2 D3: library part ZENER-C, "贴片二极管"
D10 D15: library part MOSFET-N, "贴片二极管"
D13: library part D0, "贴片肖特基"
D14: library part DIODE_Y2, "贴片二极管"
DB1 DB2: "整流桥"
EC1 EC5: library part CAPACITOR_EC_D16, "固态电容"
EC4 EC6 EC8 EC9 EC10: "电解电容"
F1: library part FUSE_BOX, "方型保险管"
FR3 R2 R3 R4 R5 R6 R7 R8 R9 R11 R13 R14 R15 R19 R23 R24 R25 R26 R27 R31 R36 R37 R38 R40 R46 R75 R76 R78 R79 R80 R81 R82 R83: library part RESISTOR_0603, "贴片电阻"
L N: library part TP_1
L1 L3 L5 L6: library part BEAD_1, "贴片磁珠"
L4: library part "INDUCTOR_ROD TYPE", "铁硅铝"
L8: library part BEAD_1, "贴片电阻"
LF1 LF2: library part "LINE FILTER_RING CORE", "共模电感"
LF2: library part "LINE FILTER_RING CORE"
NTC1: library part NTC, "热敏电阻"
Q1 Q2: "DK氮化镓功率管"
Q3 Q9 Q10: library part MOSFET-N, "NMOS管"
Q6: library part 贴片NPN三极管, "贴片三极管"
Q12: library part NPN, "场效应管"
Q17: library part MOSFET-N, "场效应管"
Q18 Q19 Q21: "贴片三极管"
R1 R33 R34: library part RESISTOR_1206, "贴片电阻"
R10 R12 RS1 RS2 RS4 RS5: library part RESISTOR_0603, "贴片合金电阻"
R28: library part 贴片电阻, "贴片电阻"
R41 R42 R45 R49 R53 R54 R74: library part RES2, "贴片电阻"
R48 R57 R70: library part RESISTOR_0805, "贴片电阻"
R61 R62 R63 R64 R65 R66 R67 R68 R69 R71 R72 R77 RX1 RX2 RX3 RX4: library part Res1, "贴片电阻"
RS6: library part Res1, "贴片合金电阻"
T1: "变压器"
T2: "PFC电感"
TYPE-C: "TYPE-C"
U1: "同步整流控制器"
U4: "东科PFC芯片"
U5 U6: library part EL1018, "贴片光耦"
U8: library part HUSB368, "协议芯片"
U18: library part DK8730, "东科AHB芯片"
ZD1 ZD2 ZD5 ZD6 ZD7: library part "ZENER DIODE", "贴片稳压管"
ZD3: library part ZENER-C, "贴片稳压管"
ZD4: library part "D Zener", "贴片稳压管"

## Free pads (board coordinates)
  oval 2x2.5 hole 1.2: 4(127.041,95.25)
  oval 3x4 hole 2 slot 3 at 90 deg: 6(81.661,116.713)
  round 4 hole 3: 6(83.618,122.325)
  oval 4x3 hole 2: 13(124.097,67.87) 13(129.482,67.846)
  round 1.524 hole 0.762: 14(117.532,67.77) 15(119.595,67.73)
  rect 3x3.5 smd far side: 16(139.897,65.958) 16(143.989,65.918)
  rect 1x2 smd far side: 16(141.976,70.211) 16(143.494,70.208) 16(158.248,64.774) 16(159.766,64.77)
  rect 3x2 smd: 16(156.182,64.81) 16(160.274,64.77)

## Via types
v1: diameter 0.5, hole 0.3, Top Layer to Bottom Layer, 439 vias
v2: diameter 0.5, hole 0.3, Top Layer to Bottom Layer, tented both sides, 64 vias
v3: diameter 0.5/0.5/0.5/0.5 (per signal layer), hole 0.3, Top Layer to Bottom Layer, tented both sides, 2 vias
v4: diameter 1, hole 0.8, Top Layer to Bottom Layer, 1 vias

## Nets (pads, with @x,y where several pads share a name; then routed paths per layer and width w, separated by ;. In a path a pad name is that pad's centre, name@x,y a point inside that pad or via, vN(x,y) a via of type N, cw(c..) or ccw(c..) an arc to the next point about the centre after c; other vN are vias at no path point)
4: 
48V: 
300-R: D1.1 NTC1.1
300V: CB1.2 L4.2 NTC1.2@95.432,70.786 R41.2 R74.2 T2.6 | length 4.8
  Bottom Layer w0.254: R41.2@95.811,79.4 R41.2@95.826,79.385
  Bottom Layer w1: R41.2@95.826,79.385 95.952,79.259 95.952,74.888 T2.6@96.094,74.747
B: Q19.3B R82.2 ZD7.2 | length 3.7
  Bottom Layer w0.5: Q19.3B@143.156,53.872 144.423,53.872 R82.2@144.653,54.102 144.78,54.229 146.558,54.229 ZD7.2@146.685,54.356
c36: C36.2 L8.1 | length 2
  Top Layer w0.2: C36.2@153.5,83.589 153.526,83.615 154.605,83.615 154.786,83.796 154.786,83.896 155.086,84.196 L8.1@155.186,84.196
C44: C44.1 R78.1 | length 1.7
  Bottom Layer w0.8: C44.1@114.496,60.439 R78.1@114.496,62.179
C48-1: C48.2 R80.2
CC1: 
CC2: 
CS2: R27.2 U4.6CS
D2-R: D2.2 R15.2 | length 1.3
  Bottom Layer w0.254: D2.2@108.372,107.131 D2.2@108.379,107.139 ; R15.2@109.704,107.139 R15.2@109.711,107.146
  Bottom Layer w0.5: D2.2@108.379,107.139 R15.2@109.704,107.139
D3-R: D3.2 R14.2 | length 1.9
  Bottom Layer w0.254: R14.2@109.89,97.375 109.839,97.324 R14.2@110.05,97.113
  Bottom Layer w0.5: D3.2@110.05,95.579 R14.2@110.05,97.113
d22: C42.1 D22.K EC4.1 Q18.2C R76.2
d23: D23.A pad.14 R78.2
D24A: D24.A R79.2 R80.1
D+: 
D-: 
FB: C10.1 R9.2 R19.1 R42.1 U4.1FB | length 0.8
  Top Layer w0.5: v2(111.789,103.511) 111.789,104.195 R42.1@111.884,104.29
GAT: R6.1 R7.1 R14.1 R15.1 U4.5GATE
GAT1: D3.1 Q2.4-G R7.2 R26.2
GAT2: D2.1 Q1.4-G R6.2 R25.2
GND: C6.1 C7.1 C10.2 C11.2 C12.1 C15.1 C16.2 C18.2 C27.2 C29.2 CB1.1 CB2.1 CY1.1 CY2.1 DB1.4 DB2.4 EC8.0 EC9.0 EC10.0 pad.6 Q12.2 R19.2 R53.2 R54.1 RS1.1 RS2.1 RS4.2 RS5.1 T2.7 U4.3GND U18.4CS ZD1.1
  other v1: 86.487,53.34 84.203,53.369 84.965,53.373 85.771,53.374 86.487,54.229 84.203,54.258 85.771,54.263 84.941,54.278 105.523,69.586 106.412,69.586 107.301,69.586 105.556,70.302 106.445,70.302 107.334,70.302 105.555,71.109 106.46,71.132 107.333,71.109 105.551,71.87 106.44,71.87 107.329,71.87 91.366,78.215 92.255,78.215 91.399,78.931 92.288,78.931 91.398,79.738 92.303,79.761 115.723,80.274 116.529,80.297 91.394,80.499 92.283,80.499 104.473,80.627 105.362,80.627 106.251,80.627 107.14,80.627 108.029,80.627 99.534,80.655 100.423,80.655 101.312,80.655 102.201,80.655 103.09,80.655 115.718,81.035 116.509,81.035 104.472,81.433 106.25,81.433 99.533,81.462 101.311,81.462 105.377,81.457 107.155,81.457 108.044,81.457 100.438,81.485 102.216,81.485 103.105,81.485 104.468,82.195 105.357,82.195 106.246,82.195 107.135,82.195 108.024,82.195 99.529,82.223 100.418,82.223 101.307,82.223 102.196,82.223 103.085,82.223 99.562,82.939 100.451,82.939 101.34,82.939 102.229,82.939 103.118,82.939 104.387,82.939 105.276,82.939 106.165,82.939 107.054,82.939 107.943,82.939 99.561,83.746 101.339,83.746 104.386,83.746 106.164,83.746 100.466,83.769 102.244,83.769 103.133,83.769 105.291,83.769 107.069,83.769 107.958,83.769 99.557,84.507 100.446,84.507 101.335,84.507 102.224,84.507 103.113,84.507 104.382,84.507 105.271,84.507 106.16,84.507 107.049,84.507 107.938,84.507 89.75,85.115 89.798,86.127 90.687,86.127 89.832,86.843 90.721,86.843 91.61,86.843 89.831,87.649 91.609,87.649 90.736,87.673 89.827,88.411 90.716,88.411 91.605,88.411
  other v2: 114.02,100.104 136.964,104.285 137.546,104.289 138.12,104.29
HV: C6.2 C7.2 C11.1 CB3.1 D1.2 D10.5 D10.6 D10.7 D10.8 D10.9 D13.1 D15.5 D15.6 D15.7 D15.8 D15.9 EC8.1 EC9.1 EC10.1 R1.1 R2.1 R3.1 R10.1 R12.1
NetBD1_1: 1.1@102.77,54.169 1.1@102.745,53.344 CB2.2 CY3.2 DB1.1 DB2.1 L4.1 R74.1 | length 6.1
  Bottom Layer w0.254: DB2.1@78.714,62.121 79.043,62.45 79.043,67.642 DB1.1@78.74,67.945
NetBD1_2: CX2.1 D9.A DB1.2 DB2.2 LF1.4 LF2.2@74.209,85.868
NetBD1_3: CX2.2 D11.A DB1.3 DB2.3 LF1.1 LF2.3@68.209,85.868
NetC1_1: C1.2 R1.2 | length 2
  Bottom Layer w0.254: R1.2@88.342,108.576 90.233,108.576 C1.2@90.286,108.524
NetC1_2: C1.1 C9.2 D10.1 D10.2 D10.3 D10.4 D15.1 D15.2 D15.3 D15.4 L1.2 L3.2 Q1.5 Q1.6 Q1.8 Q2.5 Q2.6 Q2.8
NetC2_1: C8.1 CB3.2 R4.2 T1.5
NetC3_1: 
NetC3_2: 
NetC4_2: 
NetC5_1: 
NetC5_2: 
NetC7_1: 
NetC8_2: L5.1 L6.1 U18.13VIN
NetC9_1: 
NetC9_2: L1.1 L3.1 T2.5 U4.8HV | length 25.4
  Layer 1 w0.5: T2.5@91.838,98.894 92.186,98.894 92.187,98.545 95.736,94.996 103.985,94.996 105.776,96.787 v2(105.776,103.019) ; 92.415,98.317 T2.5@92.415,99.606
  Bottom Layer w0.254: v2(105.776,103.019) v2@105.784,103.011 ; U4.8HV@107.159,103.011 U4.8HV@107.167,103.004
  Bottom Layer w0.5: v2@105.784,103.011 U4.8HV@107.159,103.011
NetC10_1: 
NetC11_1: 
NetC12_1: 
NetC12_2: C12.2 C27.1 R23.1 U4.4VCC | length 11.6
  Bottom Layer w0.2: 113.084,96.85 113.495,96.439 113.778,96.439 113.98,96.237 114.052,96.237 C12.2@114.063,96.226 ; C12.2@114.016,96.237 114.348,95.905 114.348,95.582 114.554,95.376 114.554,89.814 114.552,89.812 114.552,88.604 114.557,88.599 114.557,88.004 114.859,87.702 114.859,86.277 ; R23.1@118.075,85.768 R23.1@118.08,85.772
NetC14_1: C14.1 R24.1 | length 3.3
  Bottom Layer w0.254: R24.1@131.269,88.596 R24.1@131.319,88.546
  Bottom Layer w1.2: C14.1@128.003,88.596 R24.1@131.269,88.596
NetC14_2: C14.2 C17.2 pad.4 R8.2 U18.11HB U18.12HB U18.14HB
NetC15_2: C15.2 D7.K Q6.3 R28.2 | length 0.2
  Bottom Layer w0.254: R28.2@127.668,83.379 R28.2@127.799,83.51
NetC16_1: C16.1 R31.2 | length 1.6
  Bottom Layer w0.254: R31.2@116.268,102.743 R31.2@116.311,102.7
  Bottom Layer w0.6: C16.1@116.311,101.162 R31.2@116.311,102.7
NetC17_1: C17.1 D12.K U18.10VCCH
NetC18_1: C18.1 R31.1 U4.2COMP
NetC20_1: 
NetC21_1: 
NetC22_2: C22.2 FR3.2 U18.6FB | length 19.8
  Layer 2 w0.5: v2(138.544,101.247) 138.204,101.247 137.414,100.457 137.414,98.794 146.222,89.986 v2(146.222,87.97)
  Bottom Layer w0.254: U18.6FB@137.414,101.219 137.44,101.245 138.929,101.245 138.965,101.209 139.088,101.209 139.361,100.936 C22.2@139.361,100.836
NetC25_2: C25.2 R37.2 R38.2
NetC26_1: C25.1 pad.13@129.482,67.846 Q9.5 Q9.6 Q9.7 Q9.8 Q9.9 Q10.5 Q10.6 Q10.7 Q10.8 Q10.9 R48.2 | length 9.8
  Layer 1 w0.5: v2(125.089,53.863) 125.255,53.863 127.635,56.243 127.635,62.126 127.635,62.484
  other v1: 124.12,62.114 125.009,62.114 125.898,62.114 131.026,62.099 131.915,62.099 132.804,62.099 133.693,62.099 126.666,62.126 127.555,62.126 128.444,62.126 129.333,62.126 130.222,62.126 125.039,62.922 125.928,62.922 131.056,62.907 131.945,62.907 132.834,62.907 133.723,62.907 126.696,62.935 127.585,62.935 128.474,62.935 129.363,62.935 130.252,62.935 131.055,63.714 132.833,63.714 126.695,63.741 128.473,63.741 131.96,63.737 133.738,63.737 125.054,63.752 125.943,63.752 127.6,63.765 129.378,63.765 130.267,63.765 131.051,64.475 131.94,64.475 132.829,64.475 133.718,64.475 125.923,64.49 126.691,64.503 127.58,64.503 128.469,64.503 129.358,64.503 130.247,64.503 131.927,65.152 133.705,65.152 132.832,65.176 131.923,65.914 132.812,65.914 133.701,65.914 131.953,66.722 132.842,66.722 133.731,66.722 131.952,67.528 133.73,67.528 132.857,67.552 131.948,68.29 132.837,68.29 133.726,68.29
NetC28_1: C28.1 U1.4VDD
NetC29_1: C29.1 D14.1 R45.1 R53.1 | length 16.7
  Bottom Layer w0.254: R45.1@95.798,88.377 96.371,88.95 96.965,88.95 98.208,90.192 111.299,90.192 D14.1@111.628,90.521
NetC29_2: 
NetC30_1: 
NetC30_2: 
NetC32_2: C32.2 Q3.1 Q3.2 Q3.3 R63.2 R64.1 TYPE-C.A4B9 TYPE-C.B4A9 ZD4.2 | length 2.7
  Top Layer w0.2: R64.1@157.391,83.873 157.861,83.403 157.861,82.24 158.12,81.98 158.237,81.98 TYPE-C.B4A9@158.527,81.69 ; TYPE-C.B4A9@158.691,81.581 TYPE-C.B4A9@158.691,81.595
NetC33_2: C41.2 TYPE-C.B5CC2 U8.15 | length 7.7
  Top Layer w0.2: U8.15@155.955,79.068 156.988,79.068 157.861,79.942 157.861,80.939 158.052,81.131 ; v2(157.274,81.102) 157.282,81.094 157.447,81.094 157.483,81.131 157.971,81.131 158.052,81.131 ; TYPE-C.B5CC2@159.045,81.131 158.052,81.131
  Bottom Layer w0.2: v2(157.274,81.102) 157.751,80.626 157.751,79.261 C41.2@157.493,79.003
NetC34_2: C34.2 TYPE-C.A5CC1 U8.16 | length 6.5
  Top Layer w0.2: U8.16@155.955,79.568 156.608,79.568 157.16,80.12 v2(157.201,80.12) ; v2(157.48,77.851) 157.759,78.13 TYPE-C.A5CC1@158.859,78.13
  Layer 2 w0.2: v2(157.201,80.12) 157.48,79.841 v2(157.48,77.851)
  Bottom Layer w0.2: C34.2@157.449,76.758 157.48,76.789 v2(157.48,77.851)
NetC35_2: C35.2 R68.1 U8.22 | length 5.5
  Top Layer w0.2: U8.22@153.705,81.318 153.705,82.025 153.947,82.267 v2(153.947,82.348)
  Bottom Layer w0.3: C35.2@153.588,84.778 153.8,84.566 154.488,84.566 155.046,84.008 155.046,83.143 R68.1@155.131,83.058 154.881,82.808 154.881,82.618 154.625,82.362 v2@153.961,82.362
NetC37_1: C37.1 R67.1 U8.1
  other v2: 151.139,81.09 151.735,81.103
NetC38_1: C38.1 R71.2 | length 1.9
  Bottom Layer w0.2: C38.1@154.078,74.124 154.078,74.179 155.821,74.179 155.833,74.167 R71.2@155.833,74.118
NetC38_2: C38.2 U8.2 | length 7.8
  Top Layer w0.2: v2(150.868,80.118) 150.893,80.093 151.93,80.093 U8.2@151.955,80.068
  Layer 2 w0.2: v2(150.868,80.118) 150.949,80.118 151.064,80.003 151.131,80.003 151.7,79.434 151.7,74.992 v2(150.876,74.168)
NetC39_1: C39.1 R72.2 | length 1.8
  Bottom Layer w0.2: C39.1@154.112,72.017 154.237,72.142 155.83,72.142 R72.2@155.838,72.15
NetC39_2: C39.2 U8.4 | length 8
  Top Layer w0.2: v2(150.899,78.644) 150.913,78.644 151.338,79.068 U8.4@151.955,79.068
  Layer 1 w0.2: v2(150.878,72.81) 151.688,73.621 151.688,78.309 151.353,78.644 v2(150.899,78.644)
NetC40_1: C40.1 U8.6 | length 1.6
  Top Layer w0.2: v2(151.014,77.207) 151.018,77.211 151.018,77.784 v2(151.023,77.789) 151.104,77.789 151.384,78.068 U8.6@151.955,78.068
NetC41_2: 
NetCE1_2: 
NetCX1_1: CX1.1 LF1.3 LF2.1@74.209,92.868 LF2.2@73.959,110.087 RX1.2 RX2.2 | length 17.3
  Bottom Layer w0.254: LF2.2@73.959,110.087 74.155,109.891 74.155,105.726 75.013,104.867 75.013,104.23 75.357,103.886 RX1.2@75.575,103.886 ; RX2.2@75.1,100.822 75.1,100.839 75.62,101.359 77.063,101.359 78.005,102.302 78.005,103.873 CX1.1@77.992,103.886 75.785,103.886 RX1.2@75.575,103.886 ; RX2.2@75.513,101.359 75.403,101.468 75.403,103.479 75.286,103.597 RX1.2@75.575,103.886
NetCX1_2: CX1.2 LF1.2 LF2.3@67.959,110.087 LF2.4@68.209,92.868 RX3.1 RX4.1 | length 17.2
  Bottom Layer w0.254: CX1.2@62.992,103.886 63.334,103.544 64.018,102.86 ; LF1.2@66.289,97.434 66.472,97.617 66.472,98.758 64.246,100.984 64.246,102.632 64.018,102.86 ; LF2.3@67.959,110.087 68.155,109.891 68.155,106.675 65.121,103.641 64.799,103.641 64.018,102.86
NetD6_A: 
NetD9_K: D9.K D11.K R33.1 | length 5
  Bottom Layer w0.5: D11.K@68.504,74.661 D11.K@68.508,74.665 ; D9.K@73.468,74.665 D9.K@73.472,74.669
  Bottom Layer w1: D11.K@68.508,74.665 D9.K@73.468,74.665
